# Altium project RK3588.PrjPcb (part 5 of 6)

## Sheet RK3588_USB2.0_USB3.0.SchDoc
size C; SheetNumber: 14; SheetTotal: 22
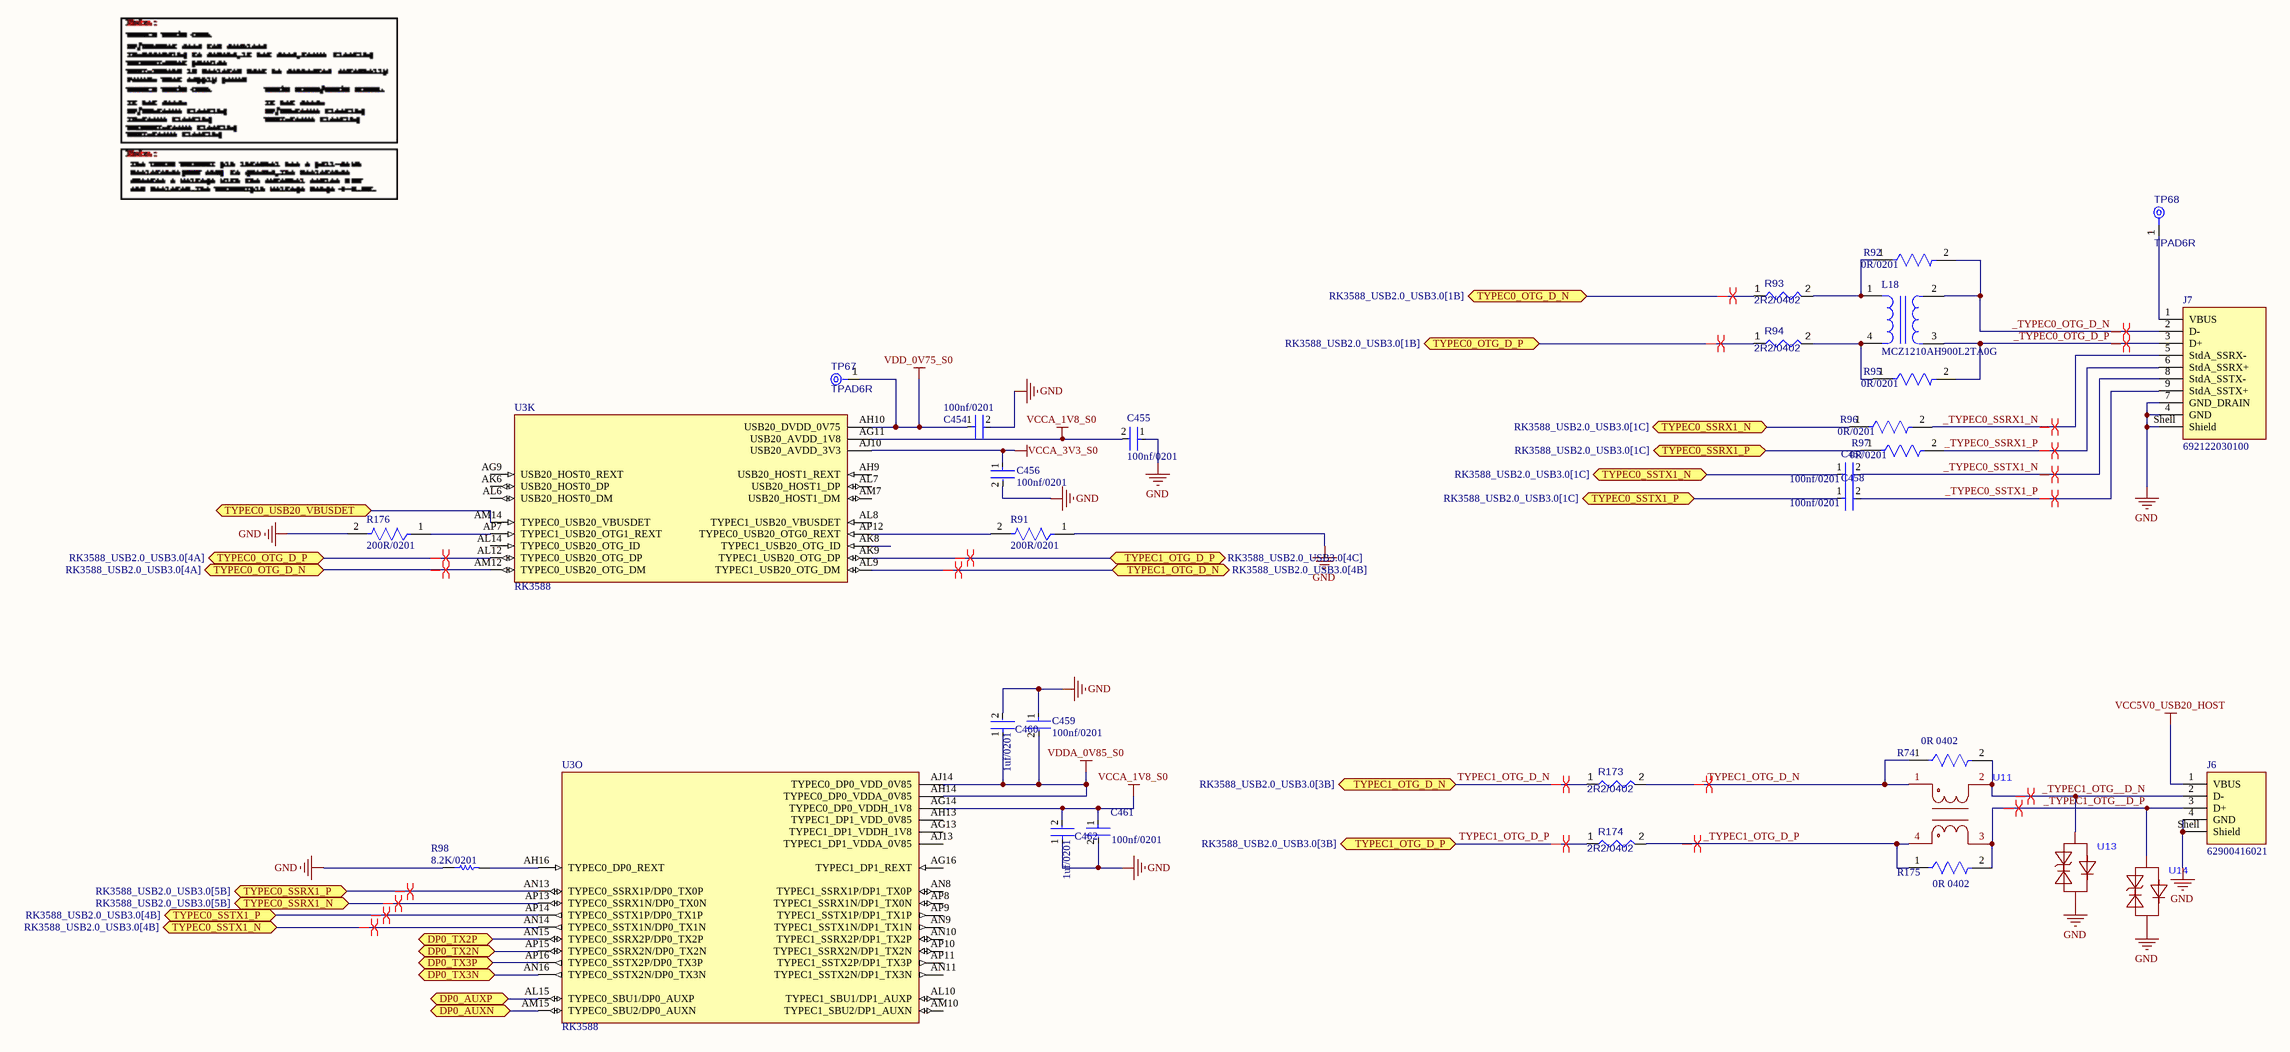
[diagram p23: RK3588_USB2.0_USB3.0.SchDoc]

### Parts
C454  100nf/0201  [FP-CL03-IPC_C]
C455  100nf/0201  [FP-CL03-IPC_C]
C456  100nf/0201  [FP-CL03-IPC_C]
C457  100nf/0201  [FP-CL03-IPC_C]
C458  100nf/0201  [FP-CL03-IPC_C]
C459  100nf/0201  [FP-CL03-IPC_C]
C460  1uf/0201  [FP-CC0201-BA-MFG]
C461  100nf/0201  [FP-CL03-IPC_C]
C462  1uf/0201  [FP-CC0201-BA-MFG]
J6  62900416021  [62900416021]
J7  692122030100  [692122030100]
L18  MCZ1210AH900L2TA0G  [FP-MCZ1210AH-MFG]
R74  0R 0402  [FP-AF0402-MFG]
R91  200R/0201  [FP-RT0201-MFG]
R92  0R/0201  [FP-RMCF0201-IPC_C]
R93  2R2/0402  [RESC0402(1005)_L]
R94  2R2/0402  [RESC0402(1005)_L]
R95  0R/0201  [FP-RMCF0201-IPC_C]
R96  0R/0201  [FP-RMCF0201-IPC_C]
R97  0R/0201  [FP-RMCF0201-IPC_C]
R98  8.2K/0201  [RESC0603X26X15ML03T05]
R173  2R2/0402  [RESC0402(1005)_L]
R174  2R2/0402  [RESC0402(1005)_L]
R175  0R 0402  [FP-AF0402-MFG]
R176  200R/0201  [FP-RT0201-MFG]
TP67  TPAD6R  [TP06R]  (no BOM)
TP68  TPAD6R  [TP06R]  (no BOM)
U3  RK3588  [BGA1088C65P34X34_2300X2300X204N]  (parts K,O of 30)
U11  (no value)  [FILTER-SMD_4P-L2.0-W1.3-BL_DLW21]
U13  (no value)  [DFN1006-2L-RD]
U14  (no value)  [DFN1006-2L-RD]

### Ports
DP0_AUXN (bidir), DP0_AUXP (bidir), DP0_TX2N (bidir), DP0_TX2P (bidir), DP0_TX3N (bidir), DP0_TX3P (bidir), TYPEC0_OTG_D_N (bidir, see RK3588_USB2.0_USB3.0[1B]), TYPEC0_OTG_D_N (bidir, see RK3588_USB2.0_USB3.0[4A]), TYPEC0_OTG_D_P (bidir, see RK3588_USB2.0_USB3.0[1B]), TYPEC0_OTG_D_P (bidir, see RK3588_USB2.0_USB3.0[4A]), TYPEC0_SSRX1_N (bidir, see RK3588_USB2.0_USB3.0[1C]), TYPEC0_SSRX1_N (bidir, see RK3588_USB2.0_USB3.0[5B]), TYPEC0_SSRX1_P (bidir, see RK3588_USB2.0_USB3.0[1C]), TYPEC0_SSRX1_P (bidir, see RK3588_USB2.0_USB3.0[5B]), TYPEC0_SSTX1_N (bidir, see RK3588_USB2.0_USB3.0[1C]), TYPEC0_SSTX1_N (bidir, see RK3588_USB2.0_USB3.0[4B]), TYPEC0_SSTX1_P (bidir, see RK3588_USB2.0_USB3.0[1C]), TYPEC0_SSTX1_P (bidir, see RK3588_USB2.0_USB3.0[4B]), TYPEC0_USB20_VBUSDET (bidir), TYPEC1_OTG_D_N (bidir, see RK3588_USB2.0_USB3.0[3B]), TYPEC1_OTG_D_N (bidir, see RK3588_USB2.0_USB3.0[4B]), TYPEC1_OTG_D_P (bidir, see RK3588_USB2.0_USB3.0[3B]), TYPEC1_OTG_D_P (bidir, see RK3588_USB2.0_USB3.0[4C])

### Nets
GND: C454.2 C455.1 C456.2 C459.1 C460.2 C461.2 C462.1 J6.4(GND) J6.Shell(Shield) J7.4(GND) J7.7(GND_DRAIN) J7.Shell(Shield) R91.1 R98.1 R176.2 U13.1 U14.1
VCC5V0_USB20_HOST: J6.1(VBUS)
VCCA_1V8_S0: C455.2 C461.1 C462.2 U3.AG11(USB20_AVDD_1V8) U3.AG14(TYPEC0_DP0_VDDH_1V8)  [project net VCCA_1V8]
VCCA_3V3_S0: C456.1 U3.AJ10(USB20_AVDD_3V3)  [project net PLDO4]
VDD_0V75_S0: C454.1 TP67.1(TP) U3.AH10(USB20_DVDD_0V75)  [project net NLDO5]
VDDA_0V85_S0: C459.2 C460.1 U3.AH14(TYPEC0_DP0_VDDA_0V85) U3.AJ14(TYPEC0_DP0_VDD_0V85)  [project net NLDO4]
_TYPEC0_OTG_D_N: J7.2(D-) L18.2 R92.2
_TYPEC0_OTG_D_P: J7.3(D+) L18.3 R95.2
_TYPEC0_SSRX1_N: J7.5(StdA_SSRX-) R96.2
_TYPEC0_SSRX1_P: J7.6(StdA_SSRX+) R97.2
_TYPEC0_SSTX1_N: C457.2 J7.8(StdA_SSTX-)
_TYPEC0_SSTX1_P: C458.2 J7.9(StdA_SSTX+)
_TYPEC1_OTG__D_N: J6.2(D-) R74.2 U11.2 U13.2
_TYPEC1_OTG__D_P: J6.3(D+) R175.2 U11.3 U14.2
_TYPEC1_OTG_D_N: R74.1 R173.2 U11.1
_TYPEC1_OTG_D_P: R174.2 R175.1 U11.4
DP0_AUXN: U3.AM15(TYPEC0_SBU2/DP0_AUXN) ; port DP0_AUXN
DP0_AUXP: U3.AL15(TYPEC0_SBU1/DP0_AUXP) ; port DP0_AUXP
DP0_TX2N: U3.AP15(TYPEC0_SSRX2N/DP0_TX2N) ; port DP0_TX2N
DP0_TX2P: U3.AN15(TYPEC0_SSRX2P/DP0_TX2P) ; port DP0_TX2P
DP0_TX3N: U3.AN16(TYPEC0_SSTX2N/DP0_TX3N) ; port DP0_TX3N
DP0_TX3P: U3.AP16(TYPEC0_SSTX2P/DP0_TX3P) ; port DP0_TX3P
TYPEC0_OTG_D_N: R93.1 U3.AM12(TYPEC0_USB20_OTG_DM) ; port TYPEC0_OTG_D_N
TYPEC0_OTG_D_P: R94.1 U3.AL12(TYPEC0_USB20_OTG_DP) ; port TYPEC0_OTG_D_P
TYPEC0_SSRX1_N: R96.1 U3.AP13(TYPEC0_SSRX1N/DP0_TX0N) ; port TYPEC0_SSRX1_N
TYPEC0_SSRX1_P: R97.1 U3.AN13(TYPEC0_SSRX1P/DP0_TX0P) ; port TYPEC0_SSRX1_P
TYPEC0_SSTX1_N: C457.1 U3.AN14(TYPEC0_SSTX1N/DP0_TX1N) ; port TYPEC0_SSTX1_N
TYPEC0_SSTX1_P: C458.1 U3.AP14(TYPEC0_SSTX1P/DP0_TX1P) ; port TYPEC0_SSTX1_P
TYPEC0_USB20_VBUSDET: U3.AM14(TYPEC0_USB20_VBUSDET) ; port TYPEC0_USB20_VBUSDET
TYPEC1_OTG_D_N: R173.1 U3.AL9(TYPEC1_USB20_OTG_DM) ; port TYPEC1_OTG_D_N
TYPEC1_OTG_D_P: R174.1 U3.AK9(TYPEC1_USB20_OTG_DP) ; port TYPEC1_OTG_D_P
NetJ7_1: J7.1(VBUS) TP68.1(TP)
NetL18_1: L18.1 R92.1 R93.2
NetL18_4: L18.4 R94.2 R95.1
NetR91_2: R91.2 U3.AP12(TYPEC0_USB20_OTG0_REXT)
NetR98_2: R98.2 U3.AH16(TYPEC0_DP0_REXT)
NetR176_1: R176.1 U3.AP7(TYPEC1_USB20_OTG1_REXT)

Not connected (* = marked no-connect by the designer): U3 AG9(USB20_HOST0_REXT) AG13(TYPEC1_DP1_VDDH_1V8) AG16(TYPEC1_DP1_REXT) AH9(USB20_HOST1_REXT) AH13(TYPEC1_DP1_VDD_0V85) AJ13(TYPEC1_DP1_VDDA_0V85) AK6(USB20_HOST0_DP) AK8(TYPEC1_USB20_OTG_ID) AL6(USB20_HOST0_DM) AL7(USB20_HOST1_DP) AL8(TYPEC1_USB20_VBUSDET) AL10(TYPEC1_SBU1/DP1_AUXP) AL14(TYPEC0_USB20_OTG_ID) AM7(USB20_HOST1_DM) AM10(TYPEC1_SBU2/DP1_AUXN) AN8(TYPEC1_SSRX1P/DP1_TX0P) AN9(TYPEC1_SSTX1N/DP1_TX1N) AN10(TYPEC1_SSRX2P/DP1_TX2P) AN11(TYPEC1_SSTX2N/DP1_TX3N) AP8(TYPEC1_SSRX1N/DP1_TX0N) AP9(TYPEC1_SSTX1P/DP1_TX1P) AP10(TYPEC1_SSRX2N/DP1_TX2N) AP11(TYPEC1_SSTX2P/DP1_TX3P)

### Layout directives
differential pair; differential pair class 90Ohm: _TYPEC0_OTG_D_N, _TYPEC0_OTG_D_P, _TYPEC0_SSRX1_N, _TYPEC0_SSRX1_P, _TYPEC0_SSTX1_N, _TYPEC0_SSTX1_P, _TYPEC1_OTG__D_N, _TYPEC1_OTG__D_P, _TYPEC1_OTG_D_N, _TYPEC1_OTG_D_P, TYPEC0_OTG_D_N, TYPEC0_OTG_D_P, TYPEC0_SSRX1_N, TYPEC0_SSRX1_P, TYPEC0_SSTX1_N, TYPEC0_SSTX1_P, TYPEC1_OTG_D_N, TYPEC1_OTG_D_P

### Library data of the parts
C454-C459 C461 = CMP-2010-00672-2: Cap Ceramic 100nF 10V X5R ±10% Pad SMD 0201 +85°C T/R; MN: CL03A104KP3NNNC
C460 C462 = CMP-03422-000660-2: 1uF 6.3V X5R ±20% 0201 Multilayer Ceramic Capacitors MLCC - SMD/SMT ROHS; Manufacturer: Yageo; Manufacturer Part Number: CC0201MRX5R5BB105; Tolerance: 0.2; Temperature Coefficient: 15%; MN: CL03A105MQ3CSNH
J6 = CMP-1502-03240-3: Wr-com; Right Angle Version 2.0; Connector SMT Socket, 30 V AC, 1.5A, 62900; Operating Supply Voltage: 30V; Contact Resistance: 20mΩ; Insulation Resistance: 1GΩ; Connector Type: USB; Number of Contacts: 4; Gender: Receptacle; USB Standard: USB 2.0
J7 = CMP-1502-03220-3: Conn USB 3.0 Type A RCP 9 POS 1.25mm Solder RA SMD 9 Terminal 1 Port T/R; Current Rating: 250mA; Insulation Resistance: 100MΩ; Number of Contacts: 9; Number of Ports: 1; Voltage Rating (AC): 30V; USB Standard: USB 3.0; Gender: Receptacle; Contact Resistance: 50mΩ
L18 = CMP-08256-000021-1: CMC 100MA 2LN 90 OHM SMD
R74 R175 = CMP-03412-048355-1: Anti-Sulfurated Chip Resistors Automotive Grade 0Ω 0402; Tolerance: 5%; MP: AF0402JR-070RL
R91 R176 = CMP-03412-012162-1: RES SMD 200 OHM 0.5% 1/20W 0201; Manufacturer Part Number: RT0201DRD07200RL; Manufacturer: Yageo; Tolerance: 0.005; Value: 200Ω; Power Rating: 0.05W; Voltage Rating: 25V; Temperature Coefficient: 25 ppm/°C
R92 R95-R97 = CMP-26527-001890-1: -55℃~+155℃ 0Ω 25V 50mW Thick Film Resistor 0201 Chip Resistor - Surface Mount ROHS; Resistance: 0R; MN: RMCF0201ZT0R00
R93 R94 R173 R174 = CMP-009-00088-2: 2R2 0.063W 5% 0402 (1005 Metric)  SMD; Power: 63mW; MN: CR0402JF02R2G
R98 = CMP-2004-01521-1: Manufacturer: KOA Speer; Part Number: RK73H1HTTC8201F
TP67 TP68 = CMP-00028-00002-2: 0.6mm round
U3 = RK3588: low power, high performance processor; MF: Fuzhou Rockchip Electronics Co
U11 = SDCW2012-2-900TF
U13 U14 = ESD5341N

## Sheet HDMI.SchDoc
size C; SheetNumber: 15; SheetTotal: 22
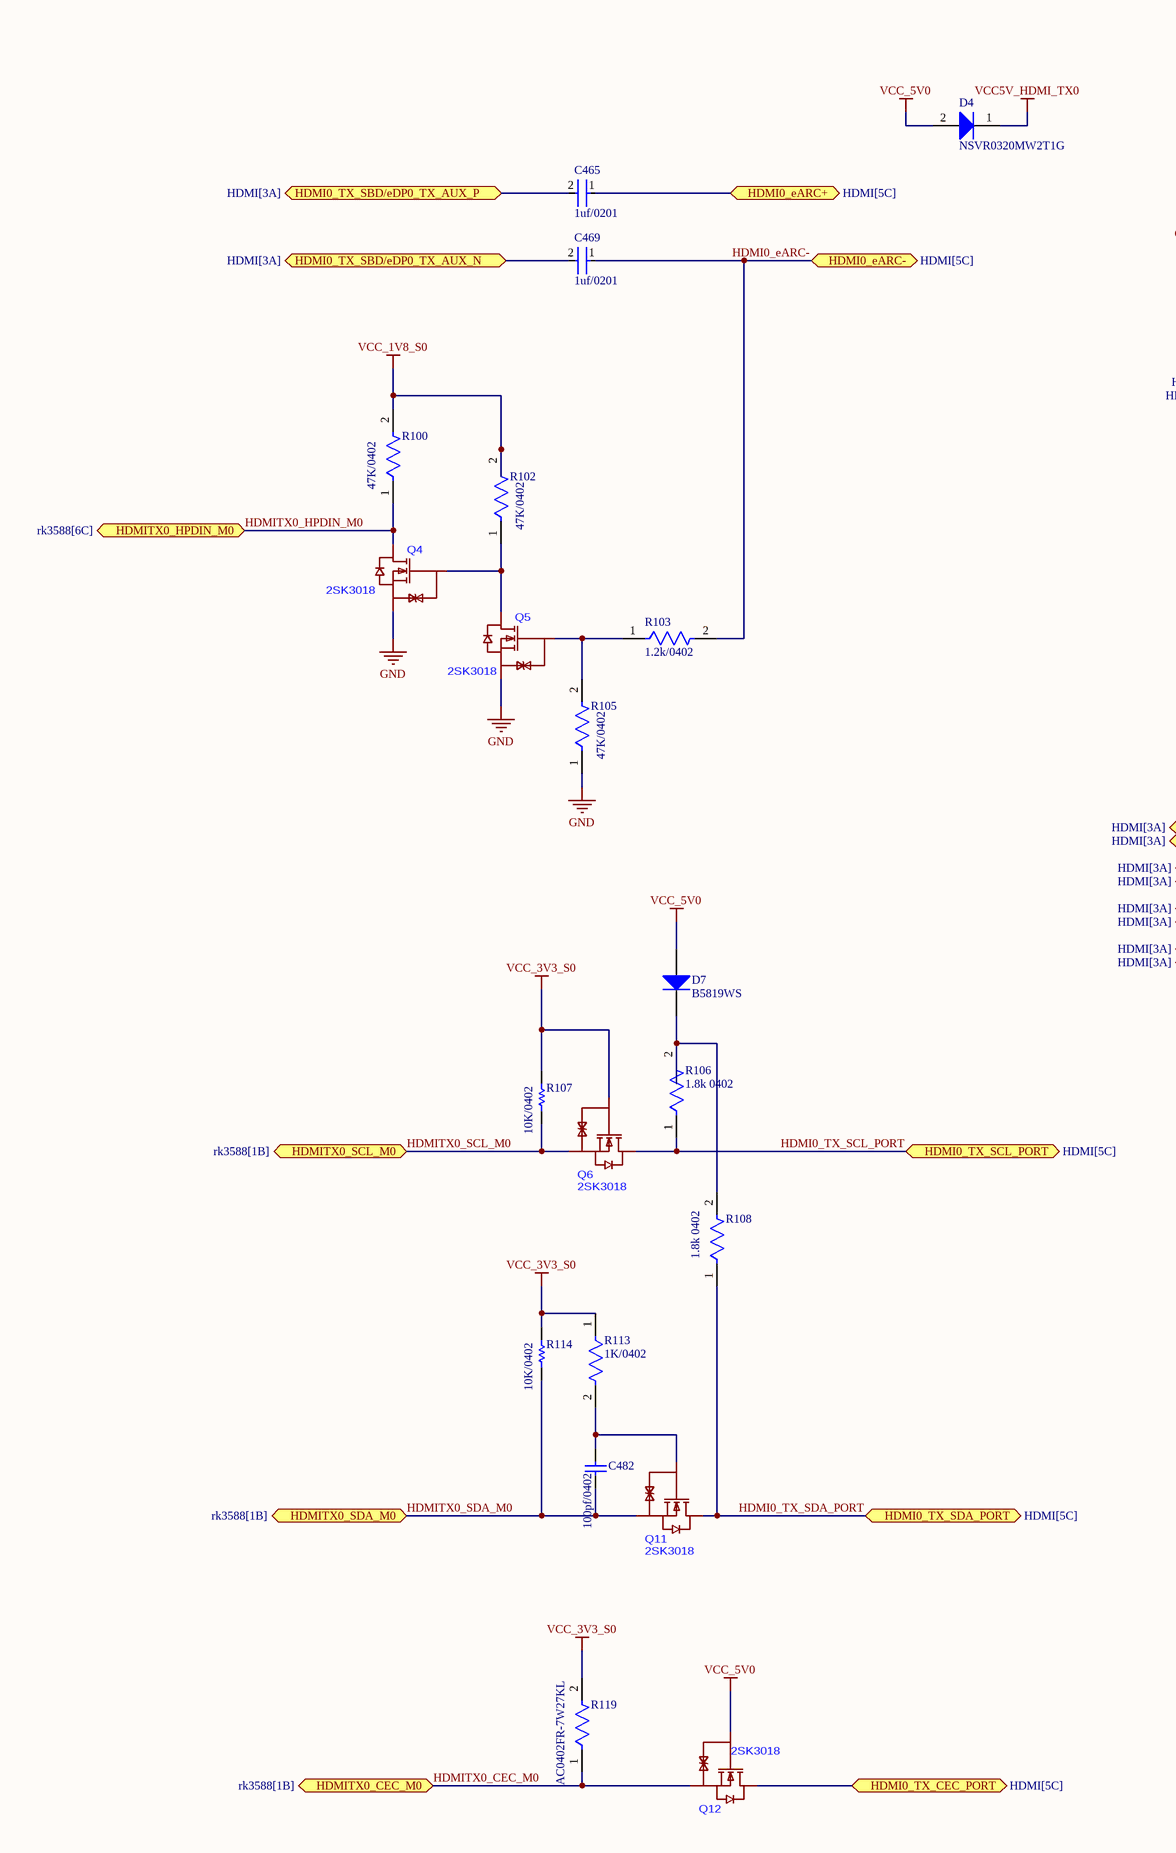
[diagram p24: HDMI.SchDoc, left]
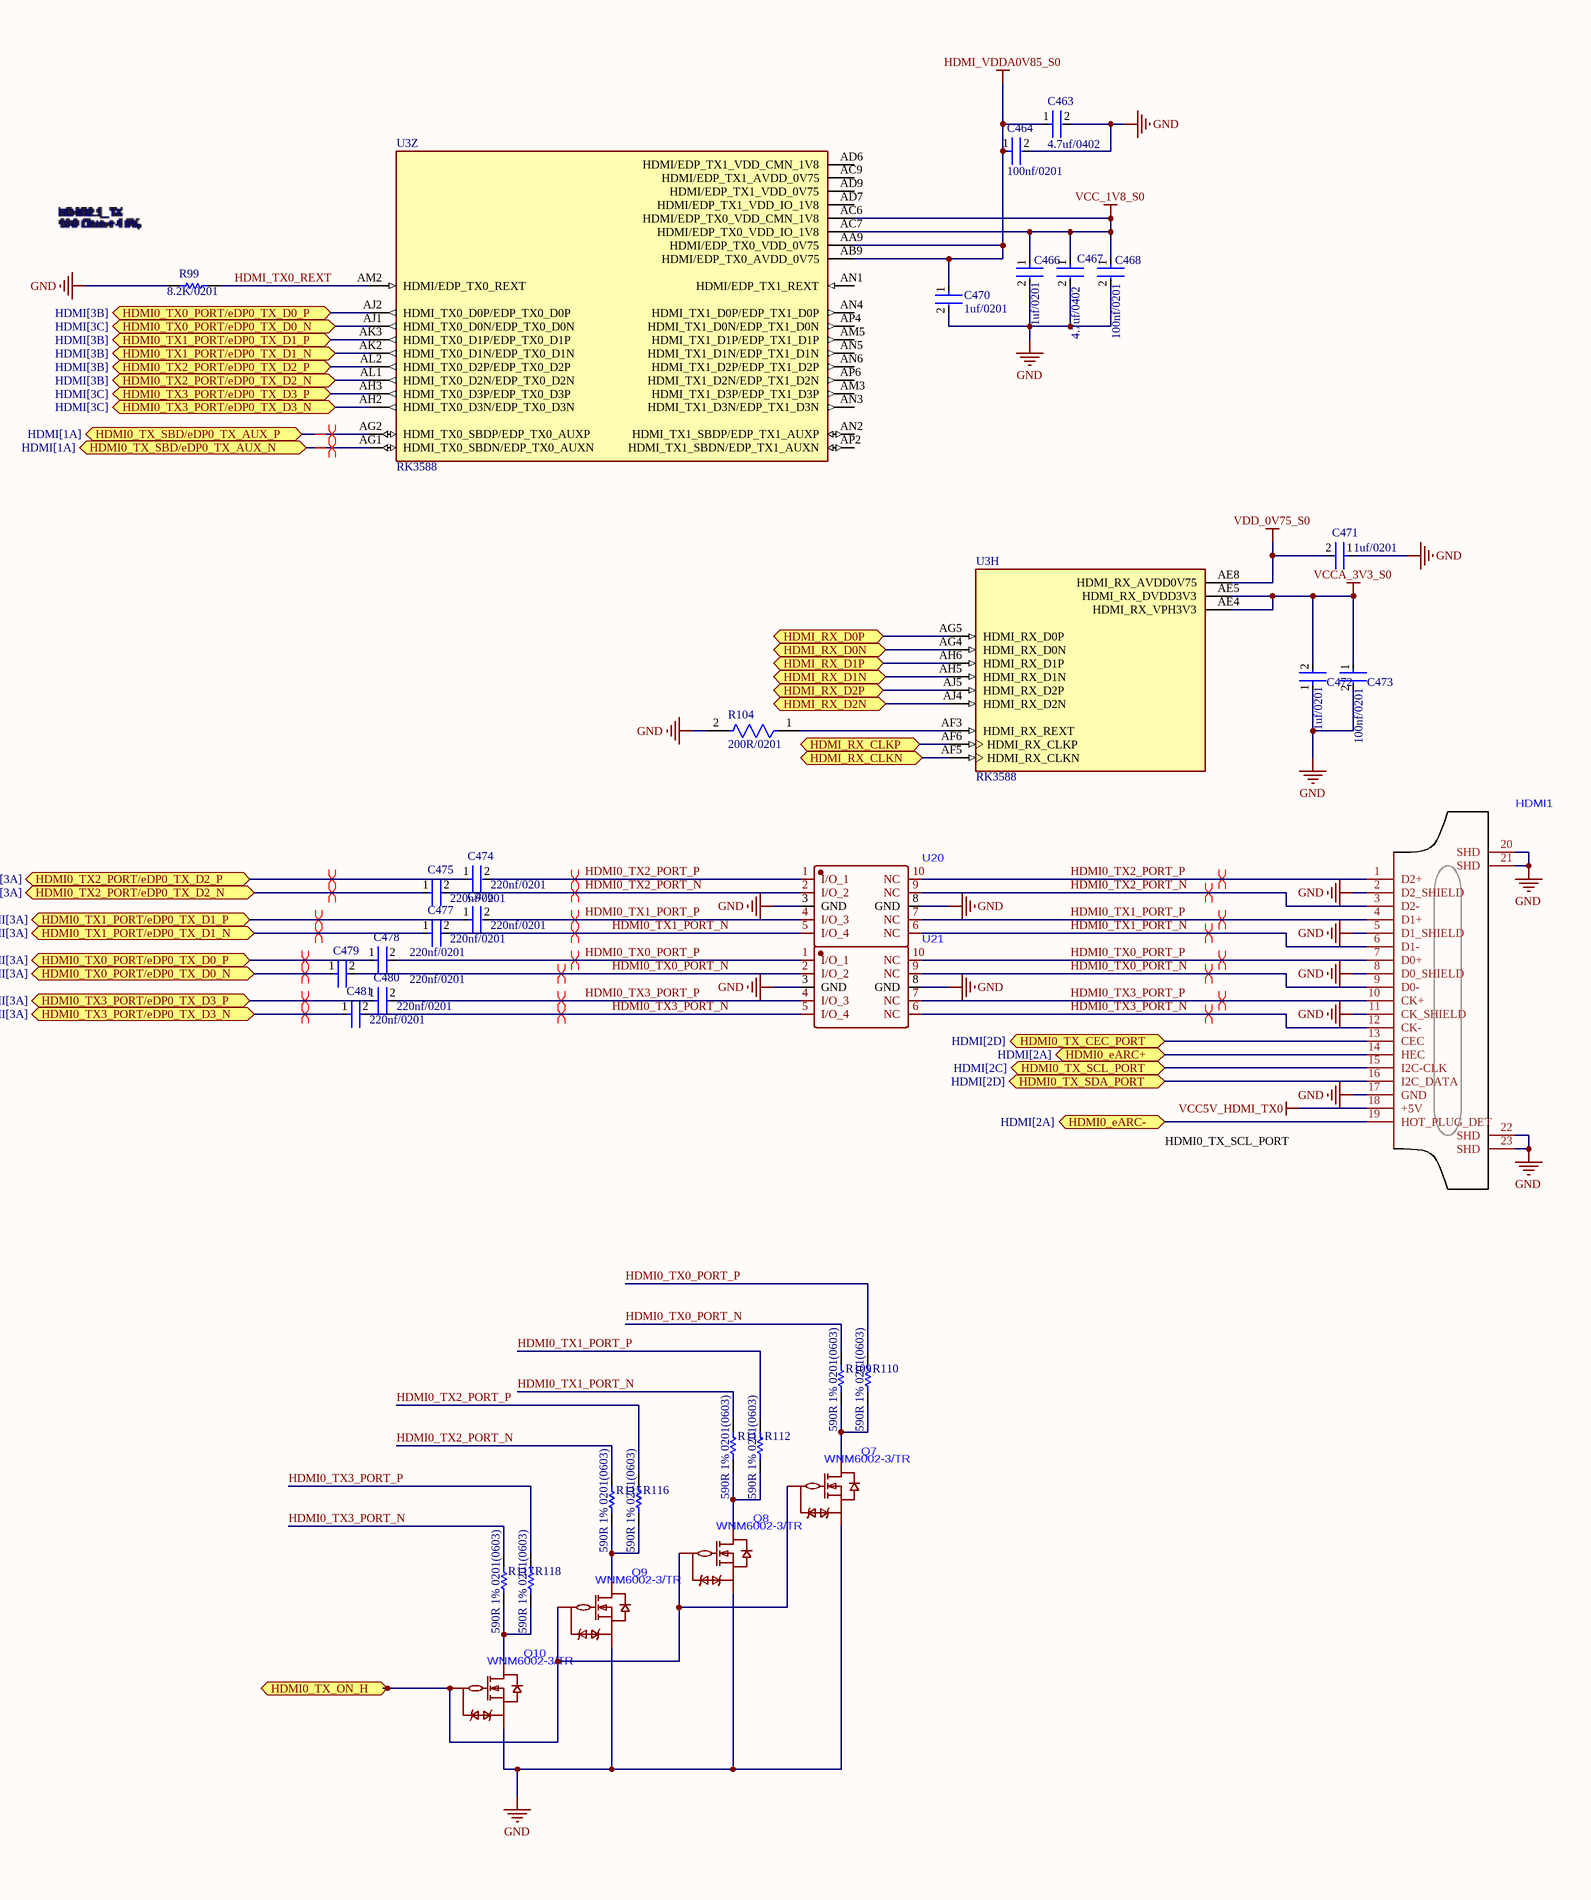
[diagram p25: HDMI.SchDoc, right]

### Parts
C463  4.7uf/0402  [FP-CC0402-MFG]
C464  100nf/0201  [FP-CL03-IPC_C]
C465  1uf/0201  [FP-CC0201-BA-MFG]
C466  1uf/0201  [FP-CC0201-BA-MFG]
C467  4.7uf/0402  [FP-CC0402-MFG]
C468  100nf/0201  [FP-CL03-IPC_C]
C469  1uf/0201  [FP-CC0201-BA-MFG]
C470  1uf/0201  [FP-CC0201-BA-MFG]
C471  1uf/0201  [FP-CC0201-BA-MFG]
C472  1uf/0201  [FP-CC0201-BA-MFG]
C473  100nf/0201  [FP-CL03-IPC_C]
C474  220nf/0201  [FP-CC0201-BA-MFG]
C475  220nf/0201  [FP-CC0201-BA-MFG]
C476  220nf/0201  [FP-CC0201-BA-MFG]
C477  220nf/0201  [FP-CC0201-BA-MFG]
C478  220nf/0201  [FP-CC0201-BA-MFG]
C479  220nf/0201  [FP-CC0201-BA-MFG]
C480  220nf/0201  [FP-CC0201-BA-MFG]
C481  220nf/0201  [FP-CC0201-BA-MFG]
C482  100pf/0402  [CAPC1005X55X25ML05T05]
D4  NSVR0320MW2T1G  [ONSC-SOD-323-2-477-02_V]
D7  B5819WS  [FAIR-SOD-323_V]
HDMI1  (no value)  [HDMI-SMD_HDMI-019S]
Q4  2SK3018  [SOT-23-3_L2.9-W1.3-P1.90-LS2.4-BR]
Q5  2SK3018  [SOT-23-3_L2.9-W1.3-P1.90-LS2.4-BR]
Q6  2SK3018  [SOT-23-3_L2.9-W1.3-P1.90-LS2.4-BR]
Q7  WNM6002-3/TR  [SOT-323-3_L2.0-W1.3-P1.30-LS2.1-BR]
Q8  WNM6002-3/TR  [SOT-323-3_L2.0-W1.3-P1.30-LS2.1-BR]
Q9  WNM6002-3/TR  [SOT-323-3_L2.0-W1.3-P1.30-LS2.1-BR]
Q10  WNM6002-3/TR  [SOT-323-3_L2.0-W1.3-P1.30-LS2.1-BR]
Q11  2SK3018  [SOT-23-3_L2.9-W1.3-P1.90-LS2.4-BR]
Q12  2SK3018  [SOT-23-3_L2.9-W1.3-P1.90-LS2.4-BR]
R99  8.2K/0201  [RESC0603X28X15NL05T05]
R100  47K/0402  [FP-CRCW0402-e3-IPC_B]
R102  47K/0402  [FP-CRCW0402-e3-IPC_B]
R103  1.2k/0402  [FP-RN73R1E-IPC_B]
R104  200R/0201  [FP-RT0201-MFG]
R105  47K/0402  [FP-CRCW0402-e3-IPC_B]
R106  1.8k 0402  [FP-RN73R1E-IPC_C]
R107  10K/0402  [RESC1005X40X25LL05T10]
R108  1.8k 0402  [FP-RN73R1E-IPC_C]
R109  590R 1% 0201(0603)  [RESC0201(0603)_L]
R110  590R 1% 0201(0603)  [RESC0201(0603)_L]
R111  590R 1% 0201(0603)  [RESC0201(0603)_L]
R112  590R 1% 0201(0603)  [RESC0201(0603)_L]
R113  1K/0402  [FP-AC0402-IPC_C]
R114  10K/0402  [RESC1005X40X25LL05T10]
R115  590R 1% 0201(0603)  [RESC0201(0603)_L]
R116  590R 1% 0201(0603)  [RESC0201(0603)_L]
R117  590R 1% 0201(0603)  [RESC0201(0603)_L]
R118  590R 1% 0201(0603)  [RESC0201(0603)_L]
R119  AC0402FR-7W27KL  [FP-AC0402-IPC_B]
U3  RK3588  [BGA1088C65P34X34_2300X2300X204N]  (parts H,Z of 30)
U20  (no value)  [DFN2510-10_L2.5-W1.0-P0.50-BL]
U21  (no value)  [DFN2510-10_L2.5-W1.0-P0.50-BL]

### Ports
HDMI0_eARC+ (bidir, see HDMI[2A]), HDMI0_eARC+ (bidir, see HDMI[5C]), HDMI0_eARC- (bidir, see HDMI[2A]), HDMI0_eARC- (bidir, see HDMI[5C]), HDMI0_TX0_PORT/eDP0_TX_D0_N (bidir, see HDMI[3A]), HDMI0_TX0_PORT/eDP0_TX_D0_N (bidir, see HDMI[3C]), HDMI0_TX0_PORT/eDP0_TX_D0_P (bidir, see HDMI[3A]), HDMI0_TX0_PORT/eDP0_TX_D0_P (bidir, see HDMI[3B]), HDMI0_TX1_PORT/eDP0_TX_D1_N (bidir, see HDMI[3A]), HDMI0_TX1_PORT/eDP0_TX_D1_N (bidir, see HDMI[3B]), HDMI0_TX1_PORT/eDP0_TX_D1_P (bidir, see HDMI[3A]), HDMI0_TX1_PORT/eDP0_TX_D1_P (bidir, see HDMI[3B]), HDMI0_TX2_PORT/eDP0_TX_D2_N (bidir, see HDMI[3A]), HDMI0_TX2_PORT/eDP0_TX_D2_N (bidir, see HDMI[3B]), HDMI0_TX2_PORT/eDP0_TX_D2_P (bidir, see HDMI[3A]), HDMI0_TX2_PORT/eDP0_TX_D2_P (bidir, see HDMI[3B]), HDMI0_TX3_PORT/eDP0_TX_D3_N (bidir, see HDMI[3A]), HDMI0_TX3_PORT/eDP0_TX_D3_N (bidir, see HDMI[3C]), HDMI0_TX3_PORT/eDP0_TX_D3_P (bidir, see HDMI[3A]), HDMI0_TX3_PORT/eDP0_TX_D3_P (bidir, see HDMI[3C]), HDMI0_TX_CEC_PORT (bidir, see HDMI[2D]), HDMI0_TX_CEC_PORT (bidir, see HDMI[5C]), HDMI0_TX_ON_H (bidir), HDMI0_TX_SBD/eDP0_TX_AUX_N (bidir, see HDMI[1A]), HDMI0_TX_SBD/eDP0_TX_AUX_N (bidir, see HDMI[3A]), HDMI0_TX_SBD/eDP0_TX_AUX_P (bidir, see HDMI[1A]), HDMI0_TX_SBD/eDP0_TX_AUX_P (bidir, see HDMI[3A]), HDMI0_TX_SCL_PORT (bidir, see HDMI[2C]), HDMI0_TX_SCL_PORT (bidir, see HDMI[5C]), HDMI0_TX_SDA_PORT (bidir, see HDMI[2D]), HDMI0_TX_SDA_PORT (bidir, see HDMI[5C]), HDMI_RX_CLKN (bidir), HDMI_RX_CLKP (bidir), HDMI_RX_D0N (bidir), HDMI_RX_D0P (bidir), HDMI_RX_D1N (bidir), HDMI_RX_D1P (bidir), HDMI_RX_D2N (bidir), HDMI_RX_D2P (bidir), HDMITX0_CEC_M0 (bidir, see rk3588[1B]), HDMITX0_HPDIN_M0 (bidir, see rk3588[6C]), HDMITX0_SCL_M0 (bidir, see rk3588[1B]), HDMITX0_SDA_M0 (bidir, see rk3588[1B])

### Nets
GND: C463.2 C464.2 C466.2 C467.2 C468.2 C470.2 C471.1 C472.1 C473.2 HDMI1.2(D2_SHIELD) HDMI1.5(D1_SHIELD) HDMI1.8(D0_SHIELD) HDMI1.11(CK_SHIELD) HDMI1.17(GND) HDMI1.20(SHD) HDMI1.21(SHD) HDMI1.22(SHD) HDMI1.23(SHD) Q4.2(S) Q5.2(S) Q7.2(S) Q8.2(S) Q9.2(S) Q10.2(S) R99.1 R104.2 R105.1 U20.3(GND) U20.8(GND) U21.3(GND) U21.8(GND)
HDMI_VDDA0V85_S0: C463.1 C464.1 C470.1 U3.AA9(HDMI/EDP_TX0_VDD_0V75) U3.AB9(HDMI/EDP_TX0_AVDD_0V75)  [project net NLDO3]
VCC5V_HDMI_TX0: D4.1(K) HDMI1.18(+5V)
VCC_1V8_S0: C466.1 C467.1 C468.1 R100.2 R102.2 U3.AC6(HDMI/EDP_TX0_VDD_CMN_1V8) U3.AC7(HDMI/EDP_TX0_VDD_IO_1V8)
VCC_3V3_S0: Q6.1(G) R107.1 R113.1 R114.1 R119.2
VCC_5V0: D4.2(A) D7.1(A) Q12.1(G)
VCCA_3V3_S0: C472.2 C473.1 U3.AE4(HDMI_RX_VPH3V3) U3.AE5(HDMI_RX_DVDD3V3)  [project net PLDO4]
VDD_0V75_S0: C471.2 U3.AE8(HDMI_RX_AVDD0V75)  [project net NLDO5]
HDMI0_eARC+: C465.1 HDMI1.14(HEC) ; port HDMI0_eARC+
HDMI0_eARC-: C469.1 HDMI1.19(HOT_PLUG_DET) R103.2 ; port HDMI0_eARC-
HDMI0_TX0_PORT/eDP0_TX_D0_N: C479.1 U3.AJ1(HDMI_TX0_D0N/EDP_TX0_D0N) ; port HDMI0_TX0_PORT/eDP0_TX_D0_N
HDMI0_TX0_PORT/eDP0_TX_D0_P: C478.1 U3.AJ2(HDMI_TX0_D0P/EDP_TX0_D0P) ; port HDMI0_TX0_PORT/eDP0_TX_D0_P
HDMI0_TX0_PORT_N: C479.2 HDMI1.9(D0-) R109.2 U21.2(I/O_2) U21.9(NC)
HDMI0_TX0_PORT_P: C478.2 HDMI1.7(D0+) R110.2 U21.1(I/O_1) U21.10(NC)
HDMI0_TX1_PORT/eDP0_TX_D1_N: C477.1 U3.AK2(HDMI_TX0_D1N/EDP_TX0_D1N) ; port HDMI0_TX1_PORT/eDP0_TX_D1_N
HDMI0_TX1_PORT/eDP0_TX_D1_P: C476.1 U3.AK3(HDMI_TX0_D1P/EDP_TX0_D1P) ; port HDMI0_TX1_PORT/eDP0_TX_D1_P
HDMI0_TX1_PORT_N: C477.2 HDMI1.6(D1-) R111.2 U20.5(I/O_4) U20.6(NC)
HDMI0_TX1_PORT_P: C476.2 HDMI1.4(D1+) R112.2 U20.4(I/O_3) U20.7(NC)
HDMI0_TX2_PORT/eDP0_TX_D2_N: C475.1 U3.AL1(HDMI_TX0_D2N/EDP_TX0_D2N) ; port HDMI0_TX2_PORT/eDP0_TX_D2_N
HDMI0_TX2_PORT/eDP0_TX_D2_P: C474.1 U3.AL2(HDMI_TX0_D2P/EDP_TX0_D2P) ; port HDMI0_TX2_PORT/eDP0_TX_D2_P
HDMI0_TX2_PORT_N: C475.2 HDMI1.3(D2-) R115.2 U20.2(I/O_2) U20.9(NC)
HDMI0_TX2_PORT_P: C474.2 HDMI1.1(D2+) R116.2 U20.1(I/O_1) U20.10(NC)
HDMI0_TX3_PORT/eDP0_TX_D3_N: C481.1 U3.AH2(HDMI_TX0_D3N/EDP_TX0_D3N) ; port HDMI0_TX3_PORT/eDP0_TX_D3_N
HDMI0_TX3_PORT/eDP0_TX_D3_P: C480.1 U3.AH3(HDMI_TX0_D3P/EDP_TX0_D3P) ; port HDMI0_TX3_PORT/eDP0_TX_D3_P
HDMI0_TX3_PORT_N: C481.2 HDMI1.12(CK-) R117.2 U21.5(I/O_4) U21.6(NC)
HDMI0_TX3_PORT_P: C480.2 HDMI1.10(CK+) R118.2 U21.4(I/O_3) U21.7(NC)
HDMI0_TX_CEC_PORT: HDMI1.13(CEC) Q12.3(D) ; port HDMI0_TX_CEC_PORT
HDMI0_TX_ON_H: Q7.1(G) Q8.1(G) Q9.1(G) Q10.1(G) ; port HDMI0_TX_ON_H
HDMI0_TX_SBD/eDP0_TX_AUX_N: C469.2 U3.AG1(HDMI_TX0_SBDN/EDP_TX0_AUXN) ; port HDMI0_TX_SBD/eDP0_TX_AUX_N
HDMI0_TX_SBD/eDP0_TX_AUX_P: C465.2 U3.AG2(HDMI_TX0_SBDP/EDP_TX0_AUXP) ; port HDMI0_TX_SBD/eDP0_TX_AUX_P
HDMI0_TX_SCL_PORT: HDMI1.15(I2C-CLK) Q6.3(D) R106.1 ; port HDMI0_TX_SCL_PORT
HDMI0_TX_SDA_PORT: HDMI1.16(I2C_DATA) Q11.3(D) R108.1 ; port HDMI0_TX_SDA_PORT
HDMI_RX_CLKN: U3.AF5(HDMI_RX_CLKN) ; port HDMI_RX_CLKN
HDMI_RX_CLKP: U3.AF6(HDMI_RX_CLKP) ; port HDMI_RX_CLKP
HDMI_RX_D0N: U3.AG4(HDMI_RX_D0N) ; port HDMI_RX_D0N
HDMI_RX_D0P: U3.AG5(HDMI_RX_D0P) ; port HDMI_RX_D0P
HDMI_RX_D1N: U3.AH5(HDMI_RX_D1N) ; port HDMI_RX_D1N
HDMI_RX_D1P: U3.AH6(HDMI_RX_D1P) ; port HDMI_RX_D1P
HDMI_RX_D2N: U3.AJ4(HDMI_RX_D2N) ; port HDMI_RX_D2N
HDMI_RX_D2P: U3.AJ5(HDMI_RX_D2P) ; port HDMI_RX_D2P
HDMI_TX0_REXT: R99.2 U3.AM2(HDMI/EDP_TX0_REXT)
HDMITX0_CEC_M0: Q12.2(S) R119.1 ; port HDMITX0_CEC_M0
HDMITX0_HPDIN_M0: Q4.3(D) R100.1 ; port HDMITX0_HPDIN_M0
HDMITX0_SCL_M0: Q6.2(S) R107.2 ; port HDMITX0_SCL_M0
HDMITX0_SDA_M0: C482.1 Q11.2(S) R114.2 ; port HDMITX0_SDA_M0
NetC482_2: C482.2 Q11.1(G) R113.2
NetD7_2: D7.2(K) R106.2 R108.2
NetQ4_1: Q4.1(G) Q5.3(D) R102.1
NetQ5_1: Q5.1(G) R103.1 R105.2
NetQ7_3: Q7.3(D) R109.1 R110.1
NetQ8_3: Q8.3(D) R111.1 R112.1
NetQ9_3: Q9.3(D) R115.1 R116.1
NetQ10_3: Q10.3(D) R117.1 R118.1
NetR104_1: R104.1 U3.AF3(HDMI_RX_REXT)

Not connected (* = marked no-connect by the designer): U3 AC9(HDMI/EDP_TX1_AVDD_0V75) AD6(HDMI/EDP_TX1_VDD_CMN_1V8) AD7(HDMI/EDP_TX1_VDD_IO_1V8) AD9(HDMI/EDP_TX1_VDD_0V75) AM3(HDMI_TX1_D3P/EDP_TX1_D3P) AM5(HDMI_TX1_D1P/EDP_TX1_D1P) AN1(HDMI/EDP_TX1_REXT) AN2(HDMI_TX1_SBDP/EDP_TX1_AUXP) AN3(HDMI_TX1_D3N/EDP_TX1_D3N) AN4(HDMI_TX1_D0P/EDP_TX1_D0P) AN5(HDMI_TX1_D1N/EDP_TX1_D1N) AN6(HDMI_TX1_D2P/EDP_TX1_D2P) AP2(HDMI_TX1_SBDN/EDP_TX1_AUXN) AP4(HDMI_TX1_D0N/EDP_TX1_D0N) AP6(HDMI_TX1_D2N/EDP_TX1_D2N)

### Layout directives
differential pair; differential pair class HDMI_100: HDMI0_TX0_PORT/eDP0_TX_D0_N, HDMI0_TX0_PORT/eDP0_TX_D0_P, HDMI0_TX0_PORT_N, HDMI0_TX0_PORT_P, HDMI0_TX1_PORT/eDP0_TX_D1_N, HDMI0_TX1_PORT/eDP0_TX_D1_P, HDMI0_TX1_PORT_N, HDMI0_TX1_PORT_P, HDMI0_TX2_PORT/eDP0_TX_D2_N, HDMI0_TX2_PORT/eDP0_TX_D2_P, HDMI0_TX2_PORT_N, HDMI0_TX2_PORT_P, HDMI0_TX3_PORT/eDP0_TX_D3_N, HDMI0_TX3_PORT/eDP0_TX_D3_P, HDMI0_TX3_PORT_N, HDMI0_TX3_PORT_P, HDMI0_TX_SBD/eDP0_TX_AUX_N, HDMI0_TX_SBD/eDP0_TX_AUX_P

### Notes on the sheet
- HDMI0_TX_SCL_PORT

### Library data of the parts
C463 C467 = CMP-03422-000823-1: 10V 4.7uF X5R ±10% 0402 Multilayer Ceramic Capacitors MLCC - SMD/SMT ROHS; Manufacturer Part Number: CC0402KRX5R6BB475; Manufacturer: YAGEO; Automotive Grade: NA; Temperature Coefficient: 30ppm/°C; Tolerance: 0.1
C464 C468 C473 = CMP-2010-00672-2: as C454-C459 on sheet RK3588_USB2.0_USB3.0
C465 C466 C469-C472 = CMP-03422-000660-2: as C460 on sheet RK3588_USB2.0_USB3.0
C474-C481 = CMP-03422-000318-1: CC0201 220 nF X5R 10.00% 10 V; Manufacturer: Yageo; Material: Ceramic; Capacitance: 220 nF; MN: CC0201KRX5R6BB224; Voltage Rating: 10 V; Temperature Coefficient: 15%; Value: 220 nF; Tolerance: 0.1
C482 = CMP-2008-01233-1: Part Number: VJ0402Y101KXAPW1BC; Manufacturer: Vitramon
D4 = CMP-1055-00467-1: Schottky Barrier Diode, 2-Pin SOD-323, Pb-Free, Tape and Reel; Manufacturer: On Semiconductor; IFSM Max (A): 5; Configuration: Single
D7 = CMP-004-00001-2: -55℃~+125℃ 1.5A 1A 40V 600mV@1A Independent SOD-323 Schottky Diodes ROHS; Manufacturer: Fairchild; Recovery Time: 4ns; Forward Voltage: 1V; Peak Reverse Current: 5uA; Forward Current: 150mA; Capacitance: -323f
HDMI1 = HDMI-019S
R99 = CMP-2004-00919-1: Manufacturer: Vishay Dale; Part Number: CRCW02018K20FKED
R100 R102 R105 = CMP-02407-007381-1: RES Thick Film, 47kΩ, 1%, 0.063W, 100ppm/°C, 0402; Max Power Dissipation: 63mW; Resistance: 47kR
R103 = CMP-04015-066543-1: 1.2kΩ ±1% 0.063W, 1/16W Chip Resistor 0402 (1005 Metric) Moisture Resistant Thin Film
R104 = CMP-03412-012162-1: as R91 on sheet RK3588_USB2.0_USB3.0
R106 R108 = CMP-04015-046155-1: 1.8kΩ ±0.1% 0.063W, 1/16W Chip Resistor 0402 (1005 Metric) Moisture Resistant Thin Film; MN: RN73R1ETTP1801B25
R107 R114 = CMP-2002-07353-1: -55℃~+155℃ 10kΩ 50V 62.5mW Thick Film Resistor ±1% ±100ppm/℃ 0402 Chip Resistor - Surface Mount ROHS; Part Number: RC0402FR-0710KL; Manufacturer: Yageo / Phycomp
R109-R112 R115-R118 = CMP-1010-00390-1: 590R 0.05W 1% 0201 (0603 Metric)  SMD; Case-Metric: 0603; Case-EIA: 0201; Value: 590.00 Ohm; MN: RC-01W5900FT
R113 = CMP-03412-047873-1: RES 1kΩ ±1% 0.063W 0402
R119 = CMP-03412-041263-1: RES 27kΩ ±1% 0.125W 0402
U3 = RK3588: as U3 on sheet RK3588_USB2.0_USB3.0
U20 U21 = ESD5304D

## Sheet Discrete Power.SchDoc
size C; SheetNumber: 16; SheetTotal: 22
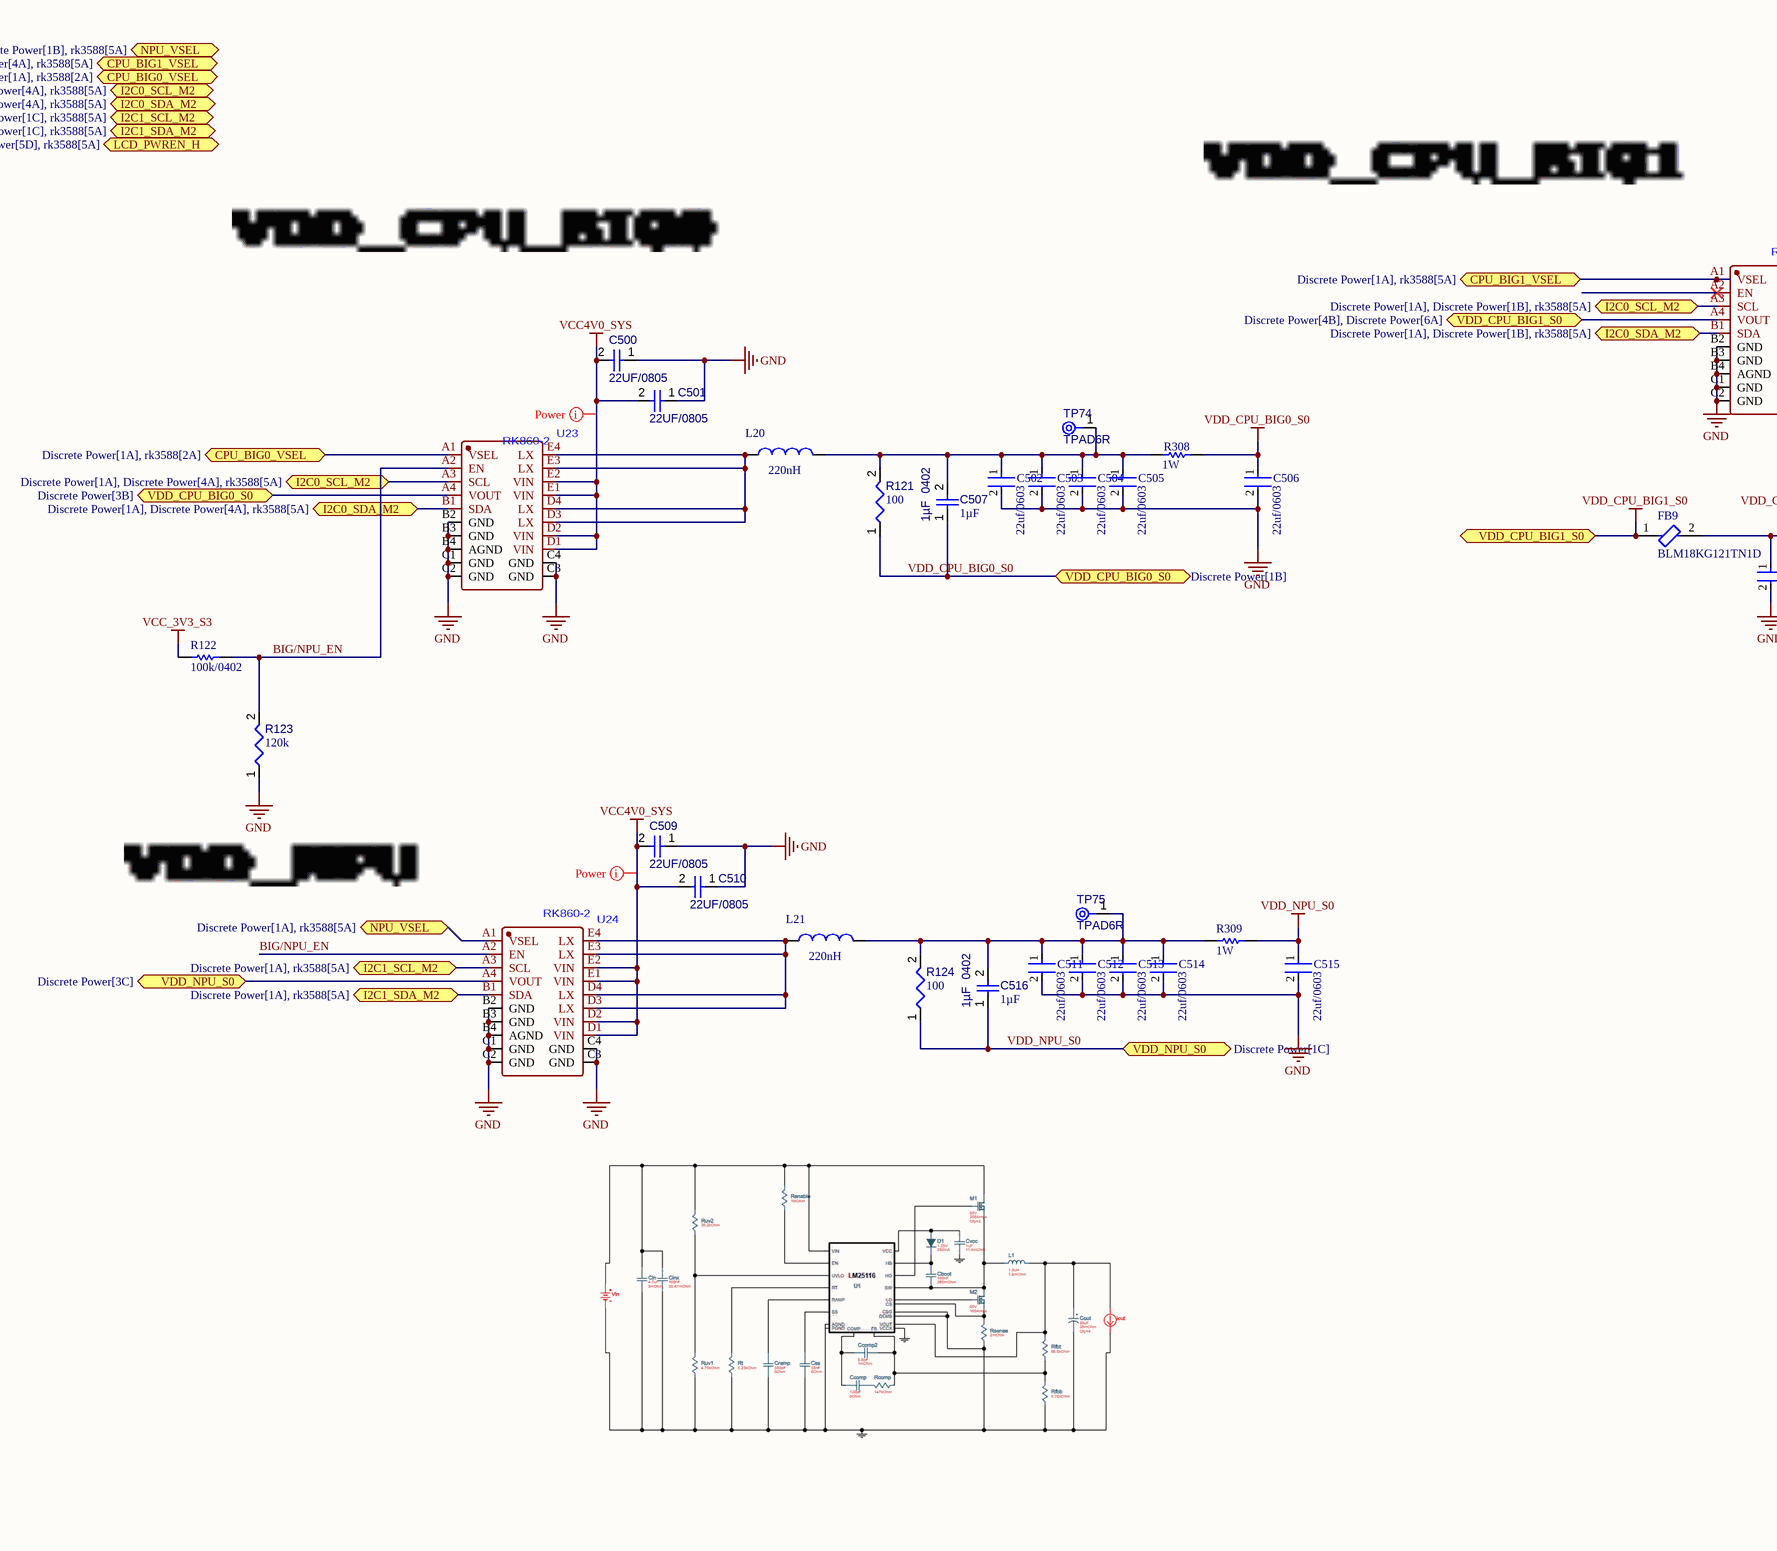
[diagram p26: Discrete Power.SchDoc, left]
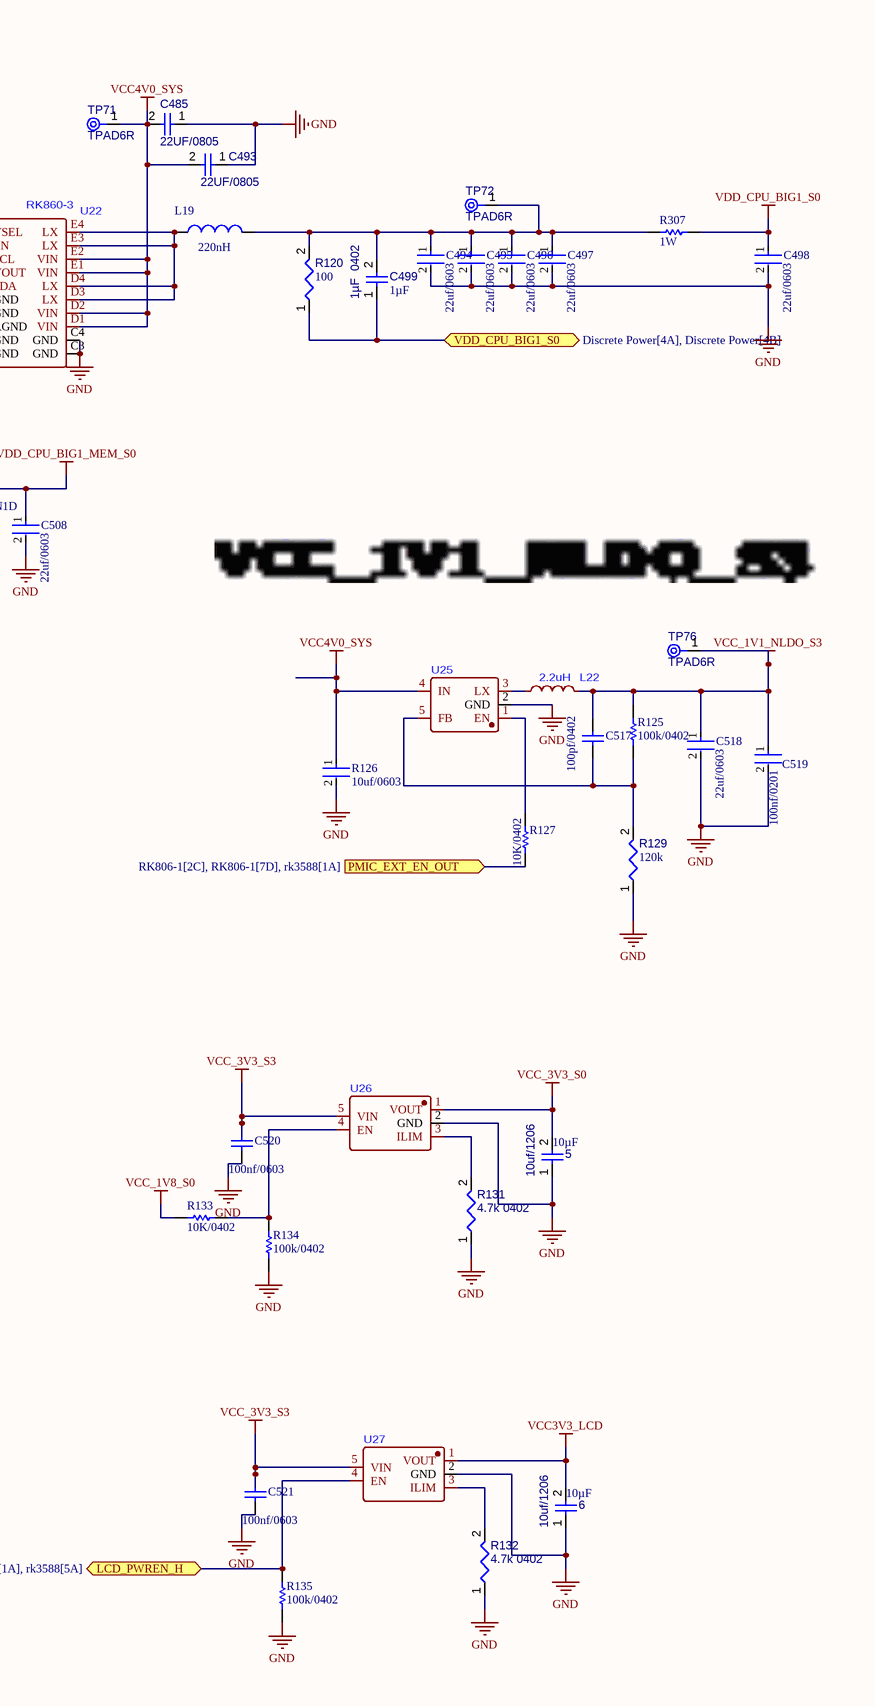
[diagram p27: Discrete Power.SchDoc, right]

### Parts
5  10uf/1206  value 10µF  [CAPC3216X180X50NL20T25]
6  10uf/1206  value 10µF  [CAPC3216X180X50NL20T25]
C485  22UF/0805  [CAPC0805(2012)145_L]
C493  22UF/0805  [CAPC0805(2012)145_L]
C494  22uf/0603  [FP-GRM188-0_2-MFG]
C495  22uf/0603  [FP-GRM188-0_2-MFG]
C496  22uf/0603  [FP-GRM188-0_2-MFG]
C497  22uf/0603  [FP-GRM188-0_2-MFG]
C498  22uf/0603  [FP-GRM188-0_2-MFG]
C499  1µF  0402  value 1µF  [CAPC0402(1005)60_L]
C500  22UF/0805  [CAPC0805(2012)145_L]
C501  22UF/0805  [CAPC0805(2012)145_L]
C502  22uf/0603  [FP-GRM188-0_2-MFG]
C503  22uf/0603  [FP-GRM188-0_2-MFG]
C504  22uf/0603  [FP-GRM188-0_2-MFG]
C505  22uf/0603  [FP-GRM188-0_2-MFG]
C506  22uf/0603  [FP-GRM188-0_2-MFG]
C507  1µF  0402  value 1µF  [CAPC0402(1005)60_L]
C508  22uf/0603  [FP-GRM188-0_2-MFG]
C509  22UF/0805  [CAPC0805(2012)145_L]
C510  22UF/0805  [CAPC0805(2012)145_L]
C511  22uf/0603  [FP-GRM188-0_2-MFG]
C512  22uf/0603  [FP-GRM188-0_2-MFG]
C513  22uf/0603  [FP-GRM188-0_2-MFG]
C514  22uf/0603  [FP-GRM188-0_2-MFG]
C515  22uf/0603  [FP-GRM188-0_2-MFG]
C516  1µF  0402  value 1µF  [CAPC0402(1005)60_L]
C517  100pf/0402  [CAPC1005X55X25ML05T05]
C518  22uf/0603  [FP-GRM188-0_2-MFG]
C519  100nf/0201  [FP-CL03-IPC_C]
C520  100nf/0603  [CAPC1608X92X38ML15T08]
C521  100nf/0603  [CAPC1608X92X38ML15T08]
FB9  BLM18KG121TN1D  [FP-BLM18-0_15-t0_6-d1_2-IPC_A]
L19  220nH  [WE-HCC_1210]
L20  220nH  [WE-HCC_1210]
L21  220nH  [WE-HCC_1210]
L22  2.2uH  [IND-SMD_L4.0-W4.0]
R120  value 100  [RESC0402(1005)_L]  (hidden comment: 100R / 0402)
R121  value 100  [RESC0402(1005)_L]  (hidden comment: 100R / 0402)
R122  100k/0402  [RESC1005X40X25NL05T10]
R123  value 120k  [RESC0402(1005)_L]  (hidden comment: 120k/0402)
R124  value 100  [RESC0402(1005)_L]  (hidden comment: 100R / 0402)
R125  100k/0402  [RESC1005X40X25NL05T10]
R126  10uf/0603  [FP-CC0603-DC-MFG]
R127  10K/0402  [RESC1005X40X25LL05T10]
R129  value 120k  [RESC0402(1005)_L]  (hidden comment: 120k/0402)
R131  4.7k 0402  [RESC0402(1005)_L]
R132  4.7k 0402  [RESC0402(1005)_L]
R133  10K/0402  [RESC1005X40X25LL05T10]
R134  100k/0402  [RESC1005X40X25NL05T10]
R135  100k/0402  [RESC1005X40X25NL05T10]
R307  value 1W  [RESC3216X60X45ML15T20]  (hidden comment: HoYH1206-1W-10mR-1%)
R308  value 1W  [RESC3216X60X45ML15T20]  (hidden comment: HoYH1206-1W-10mR-1%)
R309  value 1W  [RESC3216X60X45ML15T20]  (hidden comment: HoYH1206-1W-10mR-1%)
TP71  TPAD6R  [TP06R]  (no BOM)
TP72  TPAD6R  [TP06R]  (no BOM)
TP74  TPAD6R  [TP06R]  (no BOM)
TP75  TPAD6R  [TP06R]  (no BOM)
TP76  TPAD6R  [TP06R]  (no BOM)
U22  RK860-3  [WLCSP-20_L2.0-W1.6-R5-C4-P0.40-TL]
U23  RK860-2  [WLCSP-20_L2.0-W1.6-R5-C4-P0.40-TL]
U24  RK860-2  [WLCSP-20_L2.0-W1.6-R5-C4-P0.40-TL]
U25  (no value)  [SOT-23-5_L2.9-W1.6-P0.95-LS2.8-BL]
U26  (no value)  [SOT-23-5_L2.9-W1.6-P0.95-LS2.8-TL]
U27  (no value)  [SOT-23-5_L2.9-W1.6-P0.95-LS2.8-TL]

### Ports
CPU_BIG0_VSEL (bidir, see Discrete Power[1A], rk3588[2A]), CPU_BIG1_VSEL (bidir, see Discrete Power[1A], rk3588[5A]), CPU_BIG1_VSEL (bidir, see Discrete Power[4A], rk3588[5A]), I2C0_SCL_M2 (bidir, see Discrete Power[1A], Discrete Power[1B], rk3588[5A]), I2C0_SCL_M2 (bidir, see Discrete Power[1A], Discrete Power[4A], rk3588[5A]), I2C0_SCL_M2 (bidir, see Discrete Power[1B], Discrete Power[4A], rk3588[5A]), I2C0_SDA_M2 (bidir, see Discrete Power[1A], Discrete Power[1B], rk3588[5A]), I2C0_SDA_M2 (bidir, see Discrete Power[1A], Discrete Power[4A], rk3588[5A]), I2C0_SDA_M2 (bidir, see Discrete Power[1B], Discrete Power[4A], rk3588[5A]), I2C1_SCL_M2 (bidir, see Discrete Power[1A], rk3588[5A]), I2C1_SCL_M2 (bidir, see Discrete Power[1C], rk3588[5A]), I2C1_SDA_M2 (bidir, see Discrete Power[1A], rk3588[5A]), I2C1_SDA_M2 (bidir, see Discrete Power[1C], rk3588[5A]), LCD_PWREN_H (bidir, see Discrete Power[1A], rk3588[5A]), LCD_PWREN_H (bidir, see Discrete Power[5D], rk3588[5A]), NPU_VSEL (bidir, see Discrete Power[1A], rk3588[5A]), NPU_VSEL (bidir, see Discrete Power[1B], rk3588[5A]), PMIC_EXT_EN_OUT (in, see RK806-1[2C], RK806-1[7D], rk3588[1A]), VDD_CPU_BIG0_S0 (bidir, see Discrete Power[1B]), VDD_CPU_BIG0_S0 (bidir, see Discrete Power[3B]), VDD_CPU_BIG1_S0 (bidir, see Discrete Power[4A], Discrete Power[4B]), VDD_CPU_BIG1_S0 (bidir, see Discrete Power[4A], Discrete Power[6A]), VDD_CPU_BIG1_S0 (bidir, see Discrete Power[4B], Discrete Power[6A]), VDD_NPU_S0 (bidir, see Discrete Power[1C]), VDD_NPU_S0 (bidir, see Discrete Power[3C])

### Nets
GND: 5.1 6.1 C485.1 C493.1 C494.2 C495.2 C496.2 C497.2 C498.2 C500.1 C501.1 C502.2 C503.2 C504.2 C505.2 C506.2 C508.2 C509.1 C510.1 C511.2 C512.2 C513.2 C514.2 C515.2 C518.2 C519.2 C520.1 C521.1 R123.1 R126.2 R129.1 R131.1 R132.1 R134.2 R135.2 U22.B2(GND) U22.B3(GND) U22.B4(AGND) U22.C1(GND) U22.C2(GND) U22.C3(GND) U22.C4(GND) U23.B2(GND) U23.B3(GND) U23.B4(AGND) U23.C1(GND) U23.C2(GND) U23.C3(GND) U23.C4(GND) U24.B2(GND) U24.B3(GND) U24.B4(AGND) U24.C1(GND) U24.C2(GND) U24.C3(GND) U24.C4(GND) U25.2(GND) U26.2(GND) U27.2(GND)
VCC3V3_LCD: 6.2 U27.1(VOUT)
VCC4V0_SYS: C485.2 C493.2 C500.2 C501.2 C509.2 C510.2 R126.1 TP71.1(TP) U22.D1(VIN) U22.D2(VIN) U22.E1(VIN) U22.E2(VIN) U23.D1(VIN) U23.D2(VIN) U23.E1(VIN) U23.E2(VIN) U24.D1(VIN) U24.D2(VIN) U24.E1(VIN) U24.E2(VIN) U25.4(IN)  [project net VCC1]
VCC_1V1_NLDO_S3: C517.2 C518.1 C519.1 L22.2 R125.1 TP76.1(TP)  [project net VCC14]
VCC_1V8_S0: R133.2
VCC_3V3_S0: 5.2 U26.1(VOUT)
VCC_3V3_S3: C520.2 C521.2 R122.2 U26.5(VIN) U27.5(VIN)  [project net EMMC_VCC]
VDD_CPU_BIG0_S0: C506.1 C507.1 R121.1 R308.2 U23.A4(VOUT) ; port VDD_CPU_BIG0_S0
VDD_CPU_BIG1_MEM_S0: C508.1 FB9.2
VDD_CPU_BIG1_S0: C498.1 C499.1 FB9.1 R120.1 R307.2 U22.A4(VOUT) ; port VDD_CPU_BIG1_S0
VDD_NPU_S0: C515.1 C516.1 R124.1 R309.2 U24.A4(VOUT) ; port VDD_NPU_S0
BIG/NPU_EN: R122.1 R123.2 U23.A2(EN) U24.A2(EN)
CPU_BIG0_VSEL: U23.A1(VSEL) ; port CPU_BIG0_VSEL
CPU_BIG1_VSEL: U22.A1(VSEL) ; port CPU_BIG1_VSEL
I2C0_SCL_M2: U22.A3(SCL) U23.A3(SCL) ; port I2C0_SCL_M2
I2C0_SDA_M2: U22.B1(SDA) U23.B1(SDA) ; port I2C0_SDA_M2
I2C1_SCL_M2: U24.A3(SCL) ; port I2C1_SCL_M2
I2C1_SDA_M2: U24.B1(SDA) ; port I2C1_SDA_M2
LCD_PWREN_H: R135.1 U27.4(EN) ; port LCD_PWREN_H
NPU_VSEL: U24.A1(VSEL) ; port NPU_VSEL
PMIC_EXT_EN_OUT: R127.2 ; port PMIC_EXT_EN_OUT
NetC494_1: C494.1 C495.1 C496.1 C497.1 C499.2 L19.2 R120.2 R307.1 TP72.1(TP)
NetC502_1: C502.1 C503.1 C504.1 C505.1 C507.2 L20.2 R121.2 R308.1 TP74.1(TP)
NetC511_1: C511.1 C512.1 C513.1 C514.1 C516.2 L21.2 R124.2 R309.1 TP75.1(TP)
NetC517_1: C517.1 R125.2 R129.2 U25.5(FB)
NetL19_1: L19.1 U22.D3(LX) U22.D4(LX) U22.E3(LX) U22.E4(LX)
NetL20_1: L20.1 U23.D3(LX) U23.D4(LX) U23.E3(LX) U23.E4(LX)
NetL21_1: L21.1 U24.D3(LX) U24.D4(LX) U24.E3(LX) U24.E4(LX)
NetL22_1: L22.1 U25.3(LX)
NetR127_1: R127.1 U25.1(EN)
NetR131_2: R131.2 U26.3(ILIM)
NetR132_2: R132.2 U27.3(ILIM)
NetR133_1: R133.1 R134.1 U26.4(EN)

Not connected (* = marked no-connect by the designer): U22 A2(EN)*

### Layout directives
net class Power: VCC1

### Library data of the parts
5 6 = CMP-001-00016-6: 10uF 50V X5R ±10% 1206 Multilayer Ceramic Capacitors MLCC - SMD/SMT ROHS; Voltage Rating: 50; MN: CL31A106KBHNNNE
C485 C493 C500 C501 C509 C510 = CMP-001-00081-4: 22uF 25V X5R ±20% 0805 Multilayer Ceramic Capacitors MLCC - SMD/SMT ROHS; Voltage Rating: 16V; Tolerance: 5%; MN: CL21A226MAQNNNE
C494-C498 C502-C506 C508 C511-C515 C518 = CMP-06035-063649-1: 10V 22uF X5R ±20% 0603 Multilayer Ceramic Capacitors MLCC - SMD/SMT ROHS; MN: CL10A226MP8NUNE
C499 C507 C516 = CMP-001-00063-3: Chip Capacitor, 1µF +/-20%, 10V, 0402, Thickness 0.6 mm; Tolerance: 10%; MN: CL05A105KP5NNNC
C517 = CMP-2008-01233-1: 100pF 50V X7R ±10% 0402 Multilayer Ceramic Capacitors MLCC - SMD/SMT ROHS; Manufacturer: Vitramon; MN: VJ0402Y101KXAPW1BC
C519 = CMP-2010-00672-2: as C454-C459 on sheet RK3588_USB2.0_USB3.0
C520 C521 = CMP-2006-01140-1: Part Number: VJ0603Y104MXXAC; Manufacturer: Vitramon
FB9 = CMP-0686-00554-8: FERRITE BEAD 120 OHM 0603 1LN; Max Current Rating: 3A; DC Resistance (DCR): 30mR; Impedance: 120R; Number of Lines: 1; Test Frequency: 100MHz; Tolerance: 25%
L19-L21 = CMP-0226-00096-3: INDUCTOR, 0.22UH, 27A, 20%; Product Range: WURTH ELEKTRONIK - WE-HCC Series; Indu; Core Material: Ferrite; Self Resonant Frequency: 280MHz; Test Frequency: 100kHz; Series Resistance: 530µΩ; Shielding: Shielded; Saturation Current: 82.9A; DC Resistance (DCR): 1.1mΩ
L22 = LVF404026-2R2M-N
R120 R121 R124 = CMP-009-00065-2: 100R 0.063W 1% 0402 (1005 Metric)  SMD; Power: 63mW; MN: 0402WGF1000TCE
R122 R125 R134 R135 = CMP-2002-07343-1: Part Number: RC0402FR-07100KL; Manufacturer: Yageo / Phycomp
R123 R129 = CMP-009-00068-2: 120K 0.063W 1% 0402 (1005 Metric)  SMD; Power: 63mW; MN: 0402WGF1203TCE
R126 = CMP-00621-81932632-1: CC0603KRX5R7BB106 Multilayer Ceramic Capacitor, 10 uF, 16 V, ± 10%, X5R, 0603 [1608 Metric]; Capacitance: 10µF; Voltage Rating: 16V
R127 R133 = CMP-2002-07353-1: as R107 on sheet HDMI
R131 R132 = CMP-009-00105-2: 4K7 0.063W 1% 0402 (1005 Metric)  SMD; Power: 63mW; MN: 0402WGF4701TCE
R307-R309 = CMP-009-00002-5: 10mΩ 1W Current Sense Resistor SMD ±1% ±100ppm/℃ 1206 Current Sense Resistors / Shunt Resistors ROHS; Tolerance: 5%; Voltage Rating: 200V
TP71 TP72 TP74-TP76 = CMP-00028-00002-2: 0.6mm round
U25 = SY8089AAC
U26 U27 = SGM2576YN5G/TR

## Sheet RS232 DBG_UART.SchDoc
size A; SheetNumber: 17; SheetTotal: 22
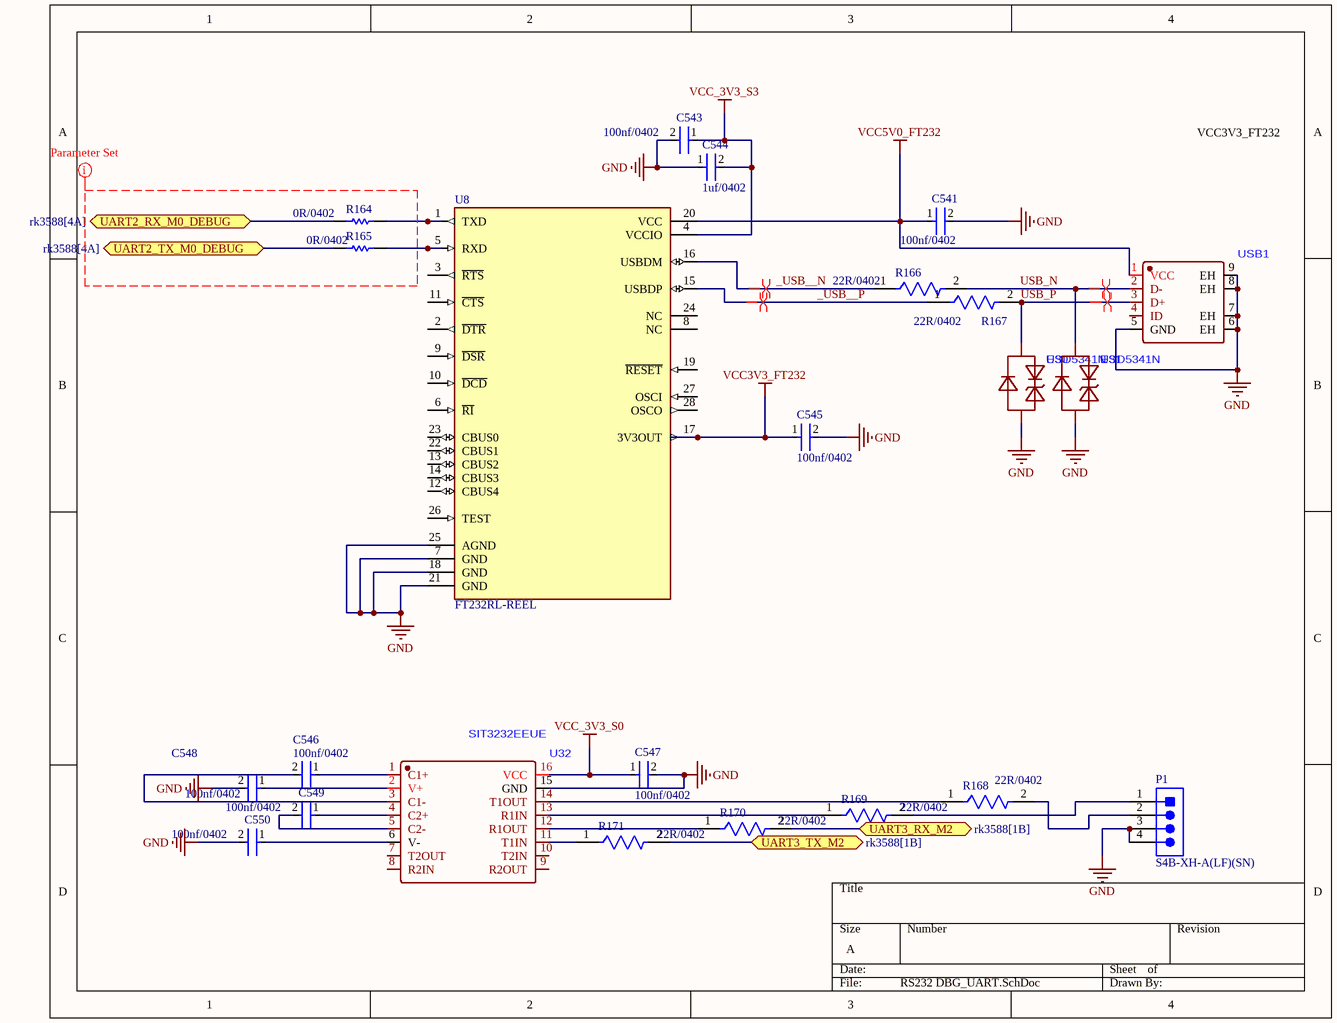
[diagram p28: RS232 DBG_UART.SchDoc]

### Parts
C541  100nf/0402  [FP-C0402-BB-MFG]
C543  100nf/0402  [FP-C0402-BB-MFG]
C544  1uf/0402  [FP-C0402C-BB-IPC_B]
C545  100nf/0402  [FP-C0402-BB-MFG]
C546  100nf/0402  [FP-C0402-BB-MFG]
C547  100nf/0402  [FP-C0402-BB-MFG]
C548  100nf/0402  [FP-C0402-BB-MFG]
C549  100nf/0402  [FP-C0402-BB-MFG]
C550  100nf/0402  [FP-C0402-BB-MFG]
P1  S4B-XH-A(LF)(SN)  [JST-S4B-XH-A(LF)(SN)_V]
R164  0R/0402  [RESC1005X40X25NL05T10]
R165  0R/0402  [RESC1005X40X25NL05T10]
R166  22R/0402  [FP-CRCW0402-e3-IPC_C]
R167  22R/0402  [FP-CRCW0402-e3-IPC_C]
R168  22R/0402  [FP-CRCW0402-e3-IPC_C]
R169  22R/0402  [FP-CRCW0402-e3-IPC_C]
R170  22R/0402  [FP-CRCW0402-e3-IPC_C]
R171  22R/0402  [FP-CRCW0402-e3-IPC_C]
U8  FT232RL-REEL  [FP-SSOP-28-MFG]
U30  ESD5341N  [DFN1006-2L-RD]
U31  ESD5341N  [DFN1006-2L-RD]
U32  SIT3232EEUE  [TSSOP-16_L5.0-W4.4-P0.65-LS6.4-BL]
USB1  (no value)  [MINI-USB-SMD_XY-5PTP-MINIUSB]

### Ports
UART2_RX_M0_DEBUG (bidir, see rk3588[4A]), UART2_TX_M0_DEBUG (bidir, see rk3588[4A]), UART3_RX_M2 (bidir, see rk3588[1B]), UART3_TX_M2 (bidir, see rk3588[1B])

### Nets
GND: C541.2 C543.2 C544.1 C545.2 C547.2 C548.2 C550.2 P1.3 P1.4 U8.7(GND) U8.18(GND) U8.21(GND) U8.25(AGND) U30.2 U31.2 U32.15(GND) USB1.5(GND) USB1.6(EH) USB1.7(EH) USB1.8(EH) USB1.9(EH)
VCC3V3_FT232: C545.1 U8.17(3V3OUT)
VCC5V0_FT232: C541.1 U8.20(VCC) USB1.1(VCC)
VCC_3V3_S0: C547.1 U32.16(VCC)
VCC_3V3_S3: C543.1 C544.2 U8.4(VCCIO)  [project net EMMC_VCC]
_USB__N: R166.1 U8.16(USBDM)
_USB__P: R167.1 U8.15(USBDP)
UART2_RX_M0_DEBUG: R164.1 ; port UART2_RX_M0_DEBUG
UART2_TX_M0_DEBUG: R165.1 ; port UART2_TX_M0_DEBUG
UART3_RX_M2: R170.2 ; port UART3_RX_M2
UART3_TX_M2: R171.2 ; port UART3_TX_M2
USB_N: R166.2 U31.1 USB1.2(D-)
USB_P: R167.2 U30.1 USB1.3(D+)
NetC546_1: C546.1 U32.1(C1+)
NetC546_2: C546.2 U32.3(C1-)
NetC548_1: C548.1 U32.2(V+)
NetC549_1: C549.1 U32.4(C2+)
NetC549_2: C549.2 U32.5(C2-)
NetC550_1: C550.1 U32.6(V-)
NetP1_1: P1.1 R169.2
NetP1_2: P1.2 R168.2
NetR164_2: R164.2 U8.1(TXD)
NetR165_2: R165.2 U8.5(RXD)
NetR168_1: R168.1 U32.14(T1OUT)
NetR169_1: R169.1 U32.13(R1IN)
NetR170_1: R170.1 U32.12(R1OUT)
NetR171_1: R171.1 U32.11(T1IN)

Not connected (* = marked no-connect by the designer): U8 2(~{DTR}) 3(~{RTS}) 6(~{RI}) 8(NC) 9(~{DSR}) 10(~{DCD}) 11(~{CTS}) 12(CBUS4) 13(CBUS2) 14(CBUS3) 19(~{RESET}) 22(CBUS1) 23(CBUS0) 24(NC) 26(TEST) 27(OSCI) 28(OSCO); U32 7(T2OUT) 8(R2IN) 9(R2OUT) 10(T2IN); USB1 4(ID)

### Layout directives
differential pair; differential pair class DBG_UART: _USB__N, _USB__P, USB_N, USB_P
net class RK_50OHM: (no net found under the mark)

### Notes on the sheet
- VCC3V3_FT232

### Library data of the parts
C541 C543 C545-C550 = CMP-2008-03082-2: CAP CER 0.1UF 16V X7R 0402; Manufacturer Part Number: C0402C104K4RACAUTO; Manufacturer: Kemet; Temperature Coefficient: 15%; Tolerance: 0.1; Capacitance: 0.10 μF; Material: Ceramic; Value: 0.10 μF
C544 = CMP-03020-034679-1: CAP CER 1UF 16V X5R 0402; Dielectric Material: Ceramic; Tolerance: 10%
P1 = CMP-002-00034-2: Male Header, Pitch 2.5 mm, 1 x 4 Position, Height 6.1 mm, Tail Length 3.4 mm, -25 to 85 degC, RoHS, Bulk; Manufacturer: JST
R164 R165 = CMP-2002-06970-1: -55℃~+155℃ 0Ω 62.5mW Thick Film Resistor ±5% 0402 Chip Resistor - Surface Mount ROHS; Part Number: RC0402JR-100RL; Manufacturer: Yageo
R166-R171 = CMP-02407-004337-1: RES Thick Film, 22Ω, 1%, 0.063W, 100ppm/°C, 0402; Resistance: 22R; Max Power Dissipation: 63mW
U8 = CMP-0078-00029-4: IC USB FS SERIAL UART 28-SSOP; Data Rate: 12Mbps; Max Supply Voltage: 5.25V; Operating Supply Current: 15mA; Number of Channels: 1; Voltage: 5V; Min Supply Voltage: 3.3V
USB1 = HMT-MINIUSB-5PTP

## Sheet Key Array.SchDoc
size B; SheetNumber: 18; SheetTotal: 22
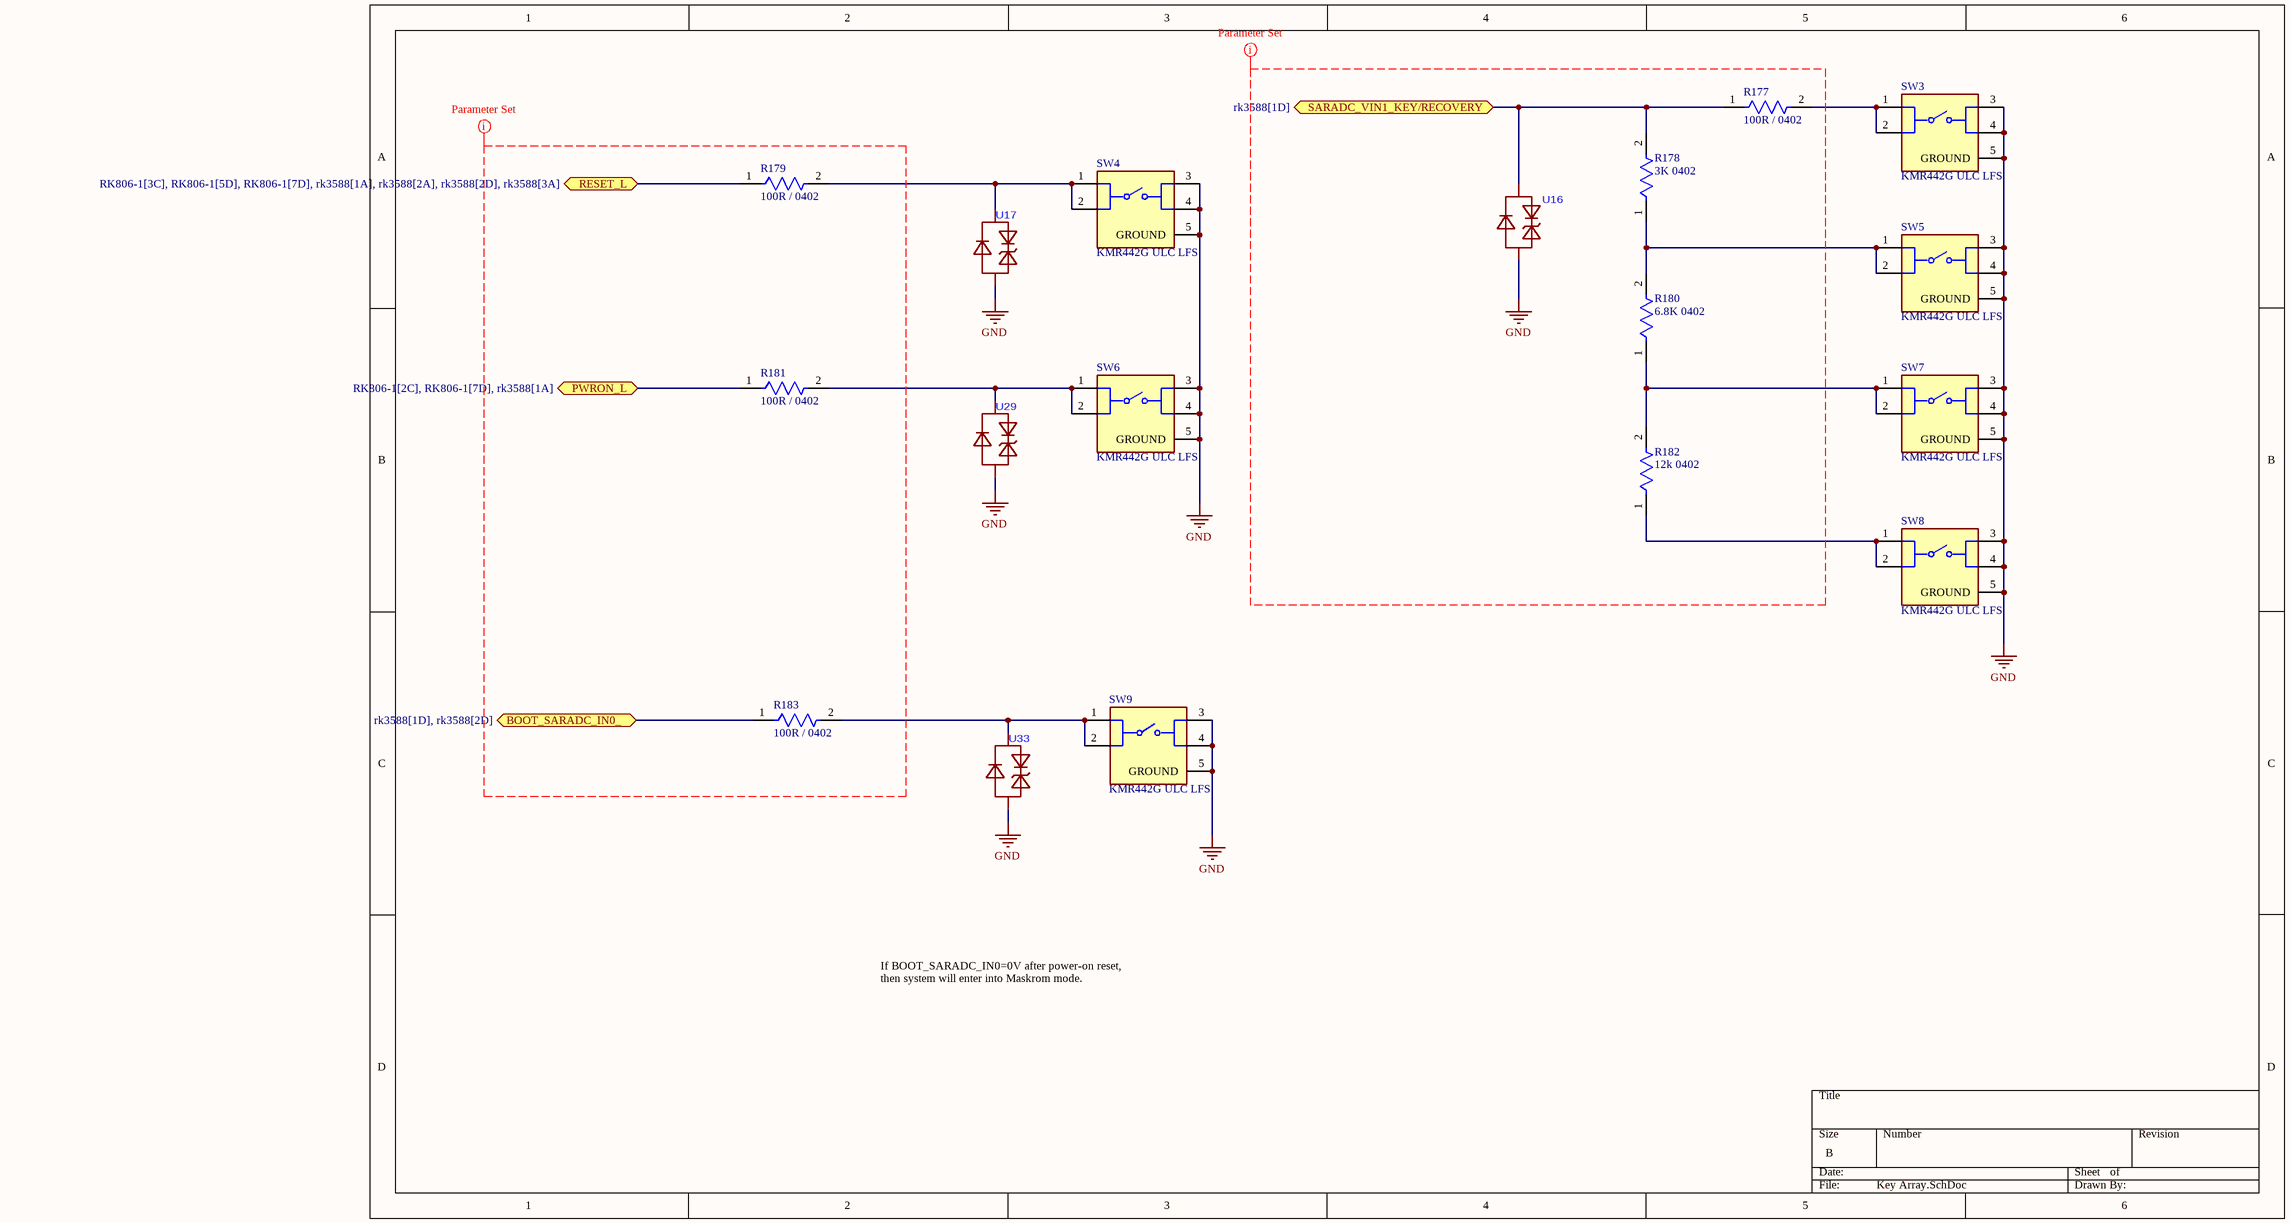
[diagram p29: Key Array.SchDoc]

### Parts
R177  100R / 0402  [FP-MCS0402-IPC_C]
R178  3K 0402  [FP-AT0402-IPC_B]
R179  100R / 0402  [FP-MCS0402-IPC_C]
R180  6.8K 0402  [FP-AC0402-MFG]
R181  100R / 0402  [FP-MCS0402-IPC_C]
R182  12k 0402  [FP-CRCW0402-e3-MFG]
R183  100R / 0402  [FP-MCS0402-IPC_C]
SW3  KMR442G ULC LFS  [FP-KMR442G_ULC_LFS-MFG]
SW4  KMR442G ULC LFS  [FP-KMR442G_ULC_LFS-MFG]
SW5  KMR442G ULC LFS  [FP-KMR442G_ULC_LFS-MFG]
SW6  KMR442G ULC LFS  [FP-KMR442G_ULC_LFS-MFG]
SW7  KMR442G ULC LFS  [FP-KMR442G_ULC_LFS-MFG]
SW8  KMR442G ULC LFS  [FP-KMR442G_ULC_LFS-MFG]
SW9  KMR442G ULC LFS  [FP-KMR442G_ULC_LFS-MFG]
U16  (no value)  [DFN1006-2L-RD]
U17  (no value)  [DFN1006-2L-RD]
U29  (no value)  [DFN1006-2L-RD]
U33  (no value)  [DFN1006-2L-RD]

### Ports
BOOT_SARADC_IN0_ (bidir, see rk3588[1D], rk3588[2D]), PWRON_L (bidir, see RK806-1[2C], RK806-1[7D], rk3588[1A]), RESET_L (bidir, see RK806-1[3C], RK806-1[5D], RK806-1[7D], rk3588[1A], rk3588[2A], rk3588[2D], rk3588[3A]), SARADC_VIN1_KEY/RECOVERY (bidir, see rk3588[1D])

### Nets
GND: SW3.3 SW3.4 SW3.5(GROUND) SW4.3 SW4.4 SW4.5(GROUND) SW5.3 SW5.4 SW5.5(GROUND) SW6.3 SW6.4 SW6.5(GROUND) SW7.3 SW7.4 SW7.5(GROUND) SW8.3 SW8.4 SW8.5(GROUND) SW9.3 SW9.4 SW9.5(GROUND) U16.2 U17.2 U29.2 U33.2
BOOT_SARADC_IN0_: R183.1 ; port BOOT_SARADC_IN0_
PWRON_L: R181.1 ; port PWRON_L
RESET_L: R179.1 ; port RESET_L
SARADC_VIN1_KEY/RECOVERY: R177.1 R178.2 U16.1 ; port SARADC_VIN1_KEY/RECOVERY
NetR177_2: R177.2 SW3.1 SW3.2
NetR178_1: R178.1 R180.2 SW5.1 SW5.2
NetR179_2: R179.2 SW4.1 SW4.2 U17.1
NetR180_1: R180.1 R182.2 SW7.1 SW7.2
NetR181_2: R181.2 SW6.1 SW6.2 U29.1
NetR182_1: R182.1 SW8.1 SW8.2
NetR183_2: R183.2 SW9.1 SW9.2 U33.1

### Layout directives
net class RK_50OHM: (no net found under the mark), GND

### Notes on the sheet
- If BOOT_SARADC_IN0=0V after power-on reset,
  then system will enter into Maskrom mode.

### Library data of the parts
R177 R179 R181 R183 = CMP-02407-010762-1: RES SMD 1.2K OHM 1% 1/10W 0402; Voltage Rating: 50V; Max Power Dissipation: 100mW; Temperature Coefficient: 50ppm/°C
R178 = CMP-03412-044565-1: Thin Film Chip Resistors Automotive Grade 3kΩ 1% 50ppm/°C 0402; MP: AT0402FRE073KL
R180 = CMP-03412-047267-1: RES 6.8kΩ ±5% 0.125W 0402; MP: AC0402JR-7W6K8L
R182 = CMP-02407-010136-1: RES Thick Film, 12kΩ, 1%, 0.063W, 100ppm/°C, 0402; Max Power Dissipation: 63mW; Resistance: 12kR; MP: CRCW040212K0FKEE
SW3-SW9 = CMP-10040-000021-1: SWITCH TACTILE SPST-NO 0.05A 32V; Actuator Type: Standard; Actuator Length: 1.1mm; Max Current Rating: 50mA; Illumination Type: Non-Illuminated; Operating Force: 4N; Switch Travel: 0.35mm; Throw Configuration: SPST; Switch Function: Off-Mom; Mechanical Life: 200000Cycles; Power Rating: 1W
U16 U17 U29 U33 = ESD5341N

## Sheet RP2350.SchDoc
size B; SheetNumber: 19; SheetTotal: 22
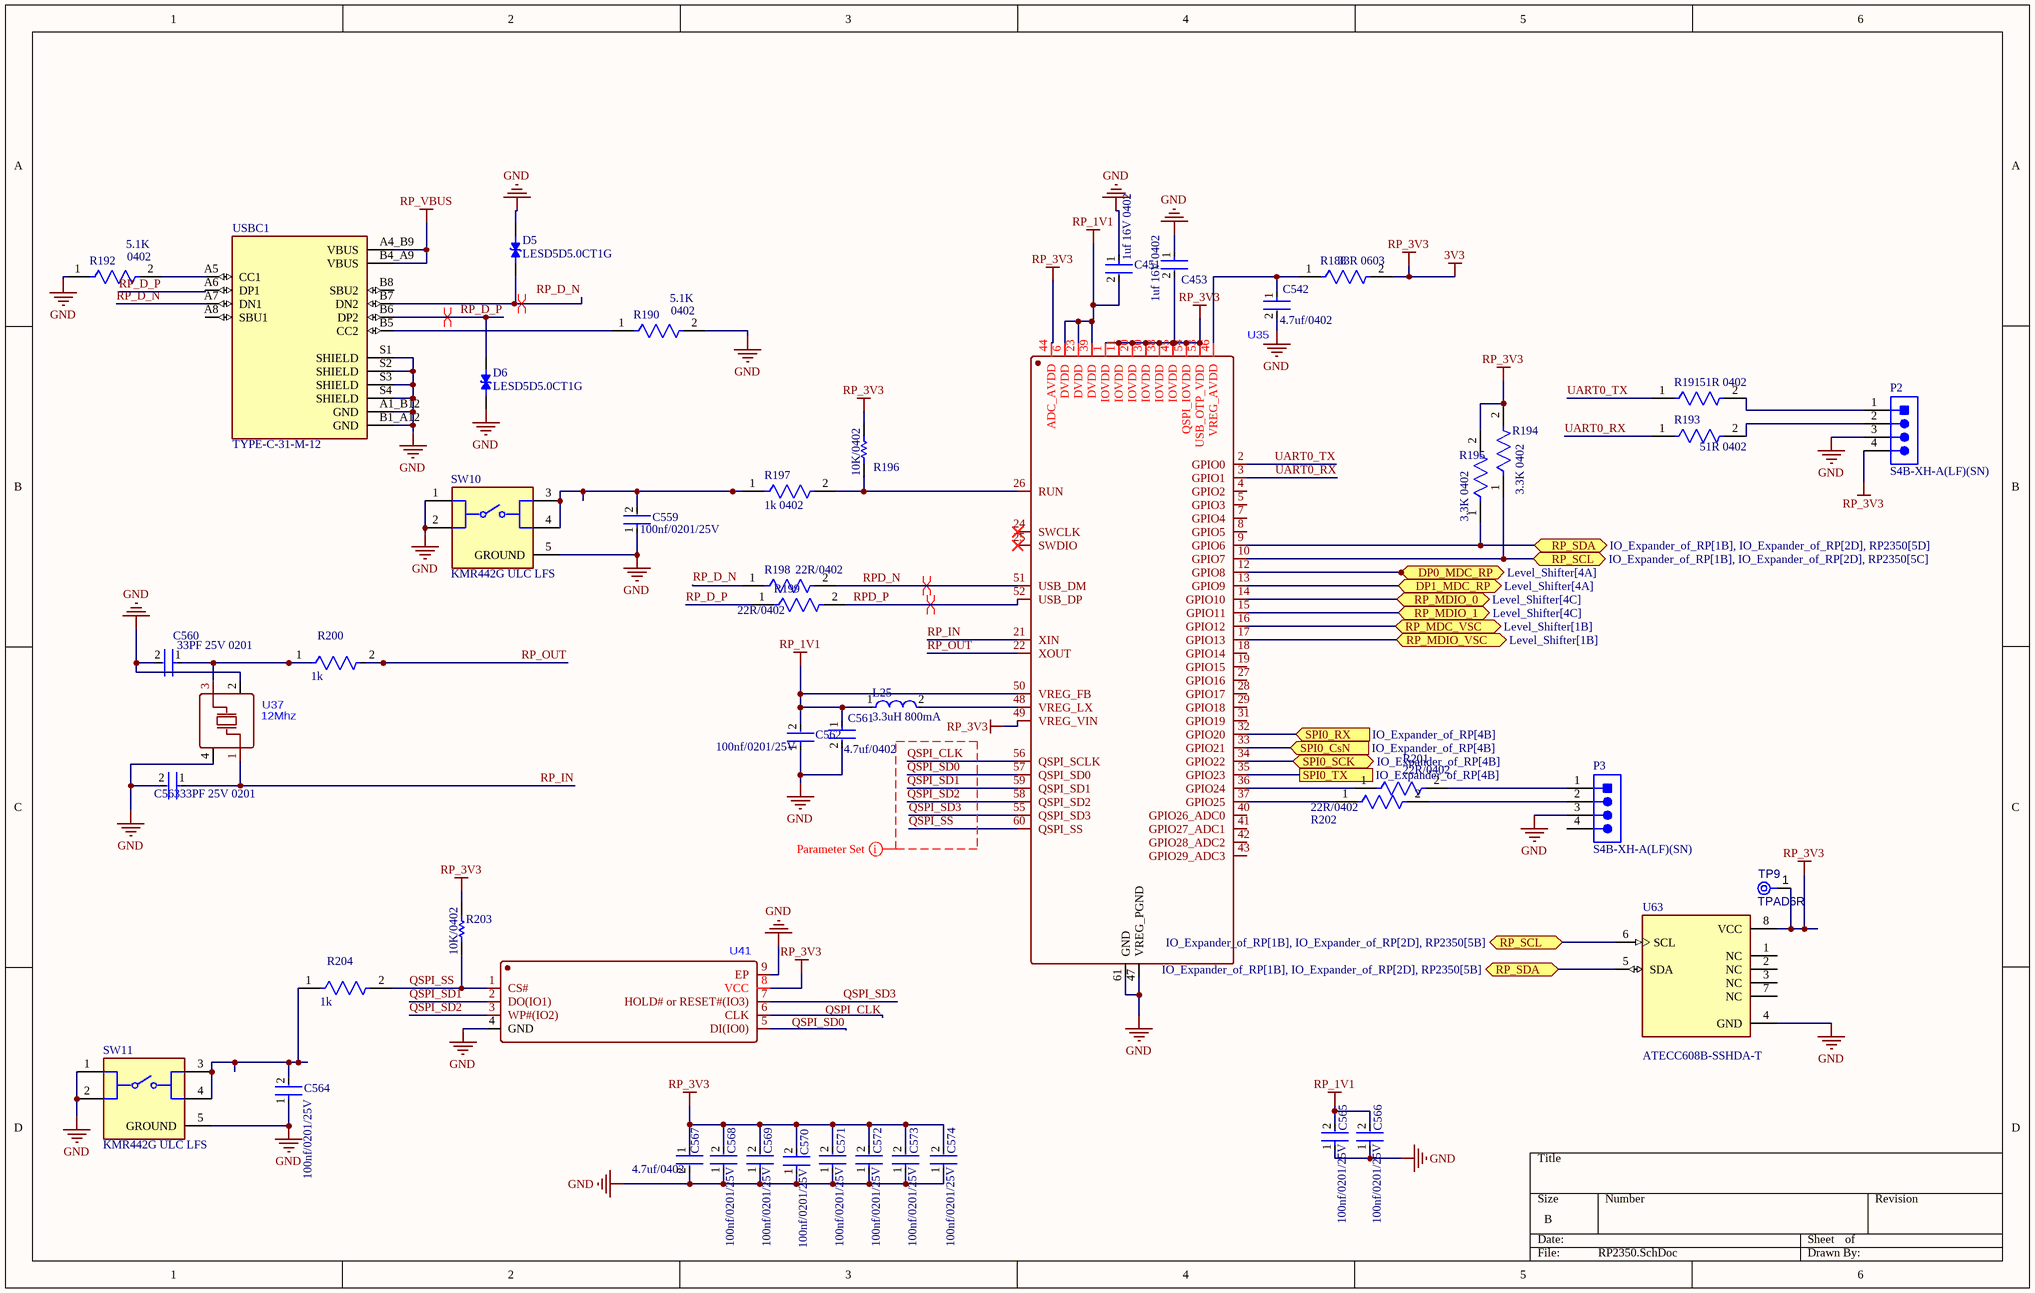
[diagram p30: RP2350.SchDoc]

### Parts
C451  1uf 16V 0402  [FP-0402-L_1_0_1-W_0_5_0_1-MFG]
C453  1uf 16V 0402  [FP-0402-L_1_0_1-W_0_5_0_1-MFG]
C542  4.7uf/0402  [FP-CC0402-MFG]
C559  100nf/0201/25V  [FP-CL03-IPC_C]
C560  33PF 25V 0201  [FP-C0201-AB-MFG]
C561  4.7uf/0402  [FP-CC0402-MFG]
C562  100nf/0201/25V  [FP-CL03-IPC_C]
C563  33PF 25V 0201  [FP-C0201-AB-MFG]
C564  100nf/0201/25V  [FP-CL03-IPC_C]
C565  100nf/0201/25V  [FP-CL03-IPC_C]
C566  100nf/0201/25V  [FP-CL03-IPC_C]
C567  4.7uf/0402  [FP-CC0402-MFG]
C568  100nf/0201/25V  [FP-CL03-IPC_C]
C569  100nf/0201/25V  [FP-CL03-IPC_C]
C570  100nf/0201/25V  [FP-CL03-IPC_C]
C571  100nf/0201/25V  [FP-CL03-IPC_C]
C572  100nf/0201/25V  [FP-CL03-IPC_C]
C573  100nf/0201/25V  [FP-CL03-IPC_C]
C574  100nf/0201/25V  [FP-CL03-IPC_C]
D5  LESD5D5.0CT1G  [TVS_LESD5D5.0CT1G]
D6  LESD5D5.0CT1G  [TVS_LESD5D5.0CT1G]
L25  3.3uH 800mA  [FP-CB2016-MFG]
P2  S4B-XH-A(LF)(SN)  [JST-S4B-XH-A(LF)(SN)_V]
P3  S4B-XH-A(LF)(SN)  [JST-S4B-XH-A(LF)(SN)_V]
R188  33R 0603  [FP-AF0603-IPC_C]
R190  value 5.1K  Case/Package: 0402  [FP-RN73R1E-IPC_C]  (hidden comment: 5.1K 0402)
R191  51R 0402  [FP-AF0402-IPC_C]
R192  value 5.1K  Case/Package: 0402  [FP-RN73R1E-IPC_C]  (hidden comment: 5.1K 0402)
R193  51R 0402  [FP-AF0402-IPC_C]
R194  3.3K 0402  [FP-RN73R1E-IPC_B]
R195  3.3K 0402  [FP-RN73R1E-IPC_B]
R196  10K/0402  [RESC1005X40X20NL05T10]
R197  1k 0402  [FP-MCS0402-IPC_C]
R198  22R/0402  [FP-CRCW0402-e3-IPC_C]
R199  22R/0402  [FP-CRCW0402-e3-IPC_C]
R200  1k  [FP-CRGCQ0402-IPC_C]
R201  22R/0402  [FP-CRCW0402-e3-IPC_C]
R202  22R/0402  [FP-CRCW0402-e3-IPC_C]
R203  10K/0402  [RESC1005X40X20NL05T10]
R204  1k  [FP-CRGCQ0402-IPC_C]
SW10  KMR442G ULC LFS  [FP-KMR442G_ULC_LFS-MFG]
SW11  KMR442G ULC LFS  [FP-KMR442G_ULC_LFS-MFG]
TP9  TPAD6R  [TP06R]  (no BOM)
U35  (no value)  [QFN-60_L7.0-W7.0-P0.40-TL-EP3.4]
U37  12Mhz  [CRYSTAL-SMD_4P-L3.2-W2.5-BL]
U41  (no value)  [WSON-8_L6.0-W8.0-P1.27-BL-EP]
U63  ATECC608B-SSHDA-T  [SOIC127P600X175-8N]
USBC1  TYPE-C-31-M-12  [HRO_TYPE-C-31-M-12]

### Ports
DP0_MDC_RP (bidir, see Level_Shifter[4A]), DP1_MDC_RP (bidir, see Level_Shifter[4A]), RP_MDC_VSC (bidir, see Level_Shifter[1B]), RP_MDIO_0 (bidir, see Level_Shifter[4C]), RP_MDIO_1 (bidir, see Level_Shifter[4C]), RP_MDIO_VSC (bidir, see Level_Shifter[1B]), RP_SCL (bidir, see IO_Expander_of_RP[1B], IO_Expander_of_RP[2D], RP2350[5B]), RP_SCL (bidir, see IO_Expander_of_RP[1B], IO_Expander_of_RP[2D], RP2350[5C]), RP_SDA (bidir, see IO_Expander_of_RP[1B], IO_Expander_of_RP[2D], RP2350[5B]), RP_SDA (bidir, see IO_Expander_of_RP[1B], IO_Expander_of_RP[2D], RP2350[5D]), SPI0_CsN (in, see IO_Expander_of_RP[4B]), SPI0_RX (in, see IO_Expander_of_RP[4B]), SPI0_SCK (bidir, see IO_Expander_of_RP[4B]), SPI0_TX (see IO_Expander_of_RP[4B])

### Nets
3V3: C453.2 C567.1 C568.2 C569.2 C570.2 C571.2 C572.2 C573.2 C574.2 P2.4 R188.2 R194.2 R195.2 R196.2 R203.2 TP9.1(TP) U35.1(IOVDD) U35.11(IOVDD) U35.20(IOVDD) U35.30(IOVDD) U35.38(IOVDD) U35.44(ADC_AVDD) U35.45(IOVDD) U35.49(VREG_VIN) U35.53(USB_OTP_VDD) U35.54(QSPI_IOVDD) U41.8(VCC) U63.8(VCC)  [also labelled RP_3V3]
GND: C451.1 C453.1 C542.2 C559.1 C560.2 C561.2 C562.1 C563.2 C564.1 C565.1 C566.1 C567.2 C568.1 C569.1 C570.1 C571.1 C572.1 C573.1 C574.1 D5.1 D6.2 P2.3 P3.3 R190.2 R192.1 SW10.1 SW10.2 SW10.5(GROUND) SW11.1 SW11.2 SW11.5(GROUND) U35.47(VREG_PGND) U35.61(GND) U37.2(GND) U37.4(GND) U41.4(GND) U41.9(EP) U63.4(GND) USBC1.A1_B12(GND) USBC1.B1_A12(GND) USBC1.S1(SHIELD) USBC1.S2(SHIELD) USBC1.S3(SHIELD) USBC1.S4(SHIELD)
RP_1V1: C451.2 C561.1 C562.2 C565.2 C566.2 L25.1 U35.6(DVDD) U35.23(DVDD) U35.39(DVDD) U35.50(VREG_FB)
RP_VBUS: USBC1.A4_B9(VBUS) USBC1.B4_A9(VBUS)
DP0_MDC_RP: U35.12(GPIO8) ; port DP0_MDC_RP
DP1_MDC_RP: U35.13(GPIO9) ; port DP1_MDC_RP
QSPI_CLK: U35.56(QSPI_SCLK) U41.6(CLK)
QSPI_SD0: U35.57(QSPI_SD0) U41.5(DI(IO0))
QSPI_SD1: U35.59(QSPI_SD1) U41.2(DO(IO1))
QSPI_SD2: U35.58(QSPI_SD2) U41.3(WP#(IO2))
QSPI_SD3: U35.55(QSPI_SD3) U41.7(HOLD#_or_RESET#(IO3))
QSPI_SS: R203.1 R204.2 U35.60(QSPI_SS) U41.1(CS#)
RP_D_N: D5.2 R198.1 USBC1.A7(DN1) USBC1.B7(DN2)
RP_D_P: D6.1 R199.1 USBC1.A6(DP1) USBC1.B6(DP2)
RP_IN: C563.1 U35.21(XIN) U37.1(XTAL)
RP_MDC_VSC: U35.16(GPIO12) ; port RP_MDC_VSC
RP_MDIO_0: U35.14(GPIO10) ; port RP_MDIO_0
RP_MDIO_1: U35.15(GPIO11) ; port RP_MDIO_1
RP_MDIO_VSC: U35.17(GPIO13) ; port RP_MDIO_VSC
RP_OUT: R200.2 U35.22(XOUT)
RP_SCL: R194.1 U35.10(GPIO7) U63.6(SCL) ; port RP_SCL
RP_SDA: R195.1 U35.9(GPIO6) U63.5(SDA) ; port RP_SDA
RPD_N: R198.2 U35.51(USB_DM)
RPD_P: R199.2 U35.52(USB_DP)
SPI0_CsN: U35.33(GPIO21) ; port SPI0_CsN
SPI0_RX: U35.32(GPIO20) ; port SPI0_RX
SPI0_SCK: U35.34(GPIO22) ; port SPI0_SCK
SPI0_TX: U35.35(GPIO23) ; port SPI0_TX
UART0_RX: R193.1 U35.3(GPIO1)
UART0_TX: R191.1 U35.2(GPIO0)
NetC542_1: C542.1 R188.1 U35.46(VREG_AVDD)
NetC559_2: C559.2 R197.1 SW10.3 SW10.4
NetC560_1: C560.1 R200.1 U37.3(XTAL)
NetC564_2: C564.2 R204.1 SW11.3 SW11.4
NetL25_2: L25.2 U35.48(VREG_LX)
NetP2_1: P2.1 R191.2
NetP2_2: P2.2 R193.2
NetP3_1: P3.1 R201.2
NetP3_2: P3.2 R202.2
NetR190_1: R190.1 USBC1.B5(CC2)
NetR192_2: R192.2 USBC1.A5(CC1)
NetR196_1: R196.1 R197.2 U35.26(RUN)
NetR201_1: R201.1 U35.36(GPIO24)
NetR202_1: R202.1 U35.37(GPIO25)

Not connected (* = marked no-connect by the designer): P3 4; U35 4(GPIO2) 5(GPIO3) 7(GPIO4) 8(GPIO5) 18(GPIO14) 19(GPIO15) 24(SWCLK)* 25(SWDIO)* 27(GPIO16) 28(GPIO17) 29(GPIO18) 31(GPIO19) 40(GPIO26_ADC0) 41(GPIO27_ADC1) 42(GPIO28_ADC2) 43(GPIO29_ADC3); U63 1(NC) 2(NC) 3(NC) 7(NC); USBC1 A8(SBU1) B8(SBU2)

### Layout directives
differential pair; differential pair class RP_USB: RP_D_N, RP_D_P, RPD_N, RPD_P
net class QSPI_RPI: QSPI_CLK, QSPI_SD0, QSPI_SD1, QSPI_SD2, QSPI_SD3, QSPI_SS

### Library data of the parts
C451 C453 = CMP-04427-002736-1: General Purpose Ceramic Capacitor, 0402, 1uF, 20%, X5R, 15%, 16V
C542 C561 C567 = CMP-03422-000823-1: as C463 on sheet HDMI
C559 C562 C564-C566 C568-C574 = CMP-2010-00672-2: as C454-C459 on sheet RK3588_USB2.0_USB3.0
C560 C563 = CMP-03020-034488-1: CAP CER 33PF 25V NP0 0201; Manufacturer Part Number: C0201C330K3GACTU; Manufacturer: KEMET; Standoff Height: 0mm; Tolerance: 0.1; Temperature Characteristic: C0G; Temperature Coefficient: 30ppm/°C; Material: Ceramic
D5 D6 = CMP-027-000000-1: Transient Voltage Suppressors for ESD Protection; MF: Leshan Radio Co.
L25 = CMP-14484-000214-1: SMD Inductors 3.3uH ±20% 0.8A 0.26Ω 0806; DC Resistance (DCR): 260mR; Saturation Current: 400mA; Test Frequency: 7.96MHz; Shielding: Unshielded; Core Material: Ferrite; Self Resonant Frequency: 55MHz
P2 P3 = CMP-002-00034-2: as P1 on sheet RS232 DBG_UART
R188 = CMP-03412-046795-1: Anti-Sulfurated Chip Resistors Automotive Grade 33Ω 1% 100ppm/°C 0603; Max Power Dissipation: 100mW; MN: AF0603FR-0733RL
R190 R192 = CMP-04015-008529-1: 5.1kΩ ±1% 0.063W, 1/16W Chip Resistor 0402 (1005 Metric) Moisture Resistant Thin Film; MN: RN73R1ETTP5101F25
R191 R193 = CMP-03412-039875-1: Anti-Sulfurated Chip Resistors Automotive Grade 51Ω 5% 100ppm/°C 0402; Max Power Dissipation: 63mW
R194 R195 = CMP-04015-026447-1: 3.3kΩ ±1% 0.063W, 1/16W Chip Resistor 0402 (1005 Metric) Moisture Resistant Thin Film
R196 R203 = CMP-2002-01682-1: Manufacturer: Vishay BCcomponents; Part Number: TNPW040210K0DEED
R197 = CMP-2002-02445-2: RES SMD 1.2K OHM 1% 1/10W 0402; Resistance: 1kR; Tolerance: 0.1%; Max Power Dissipation: 63mW; Temperature Coefficient: 25ppm/°C; MN: MCS04020D1001BE000
R198 R199 R201 R202 = CMP-02407-004337-1: as R166 on sheet RS232 DBG_UART
R200 R204 = CMP-03211-006314-1: CRGCQ0402 1KΩ 1% ±100ppm/°C 50V; Manufacturer Part Number: CRGCQ0402F1K0; Manufacturer: TE Connectivity; Power Rating: 0.0625W; Tolerance: 0.01
SW10 SW11 = CMP-10040-000021-1: as SW3 on sheet Key Array
TP9 = CMP-00028-00002-2: 0.6mm round
U35 = RP2350A
U37 = C9002: MN: ABM8-272-T3
U41 = W25Q128JVEIQ TR
U63 = ATECC608B-SSHDA-T: Security ICs / Authentication ICs ECC/ECDH, I2C, SOIC T/R; MF: Microchip Technology
USBC1 = TYPE-C-31-M-12: USB Connectors 24 Receptacle 1 8.94*7.3mm RoHS; MF: HRO Electronics Co., Ltd.

## Sheet IO_Expander_of_RP.SchDoc
size C; SheetNumber: 20; SheetTotal: 22
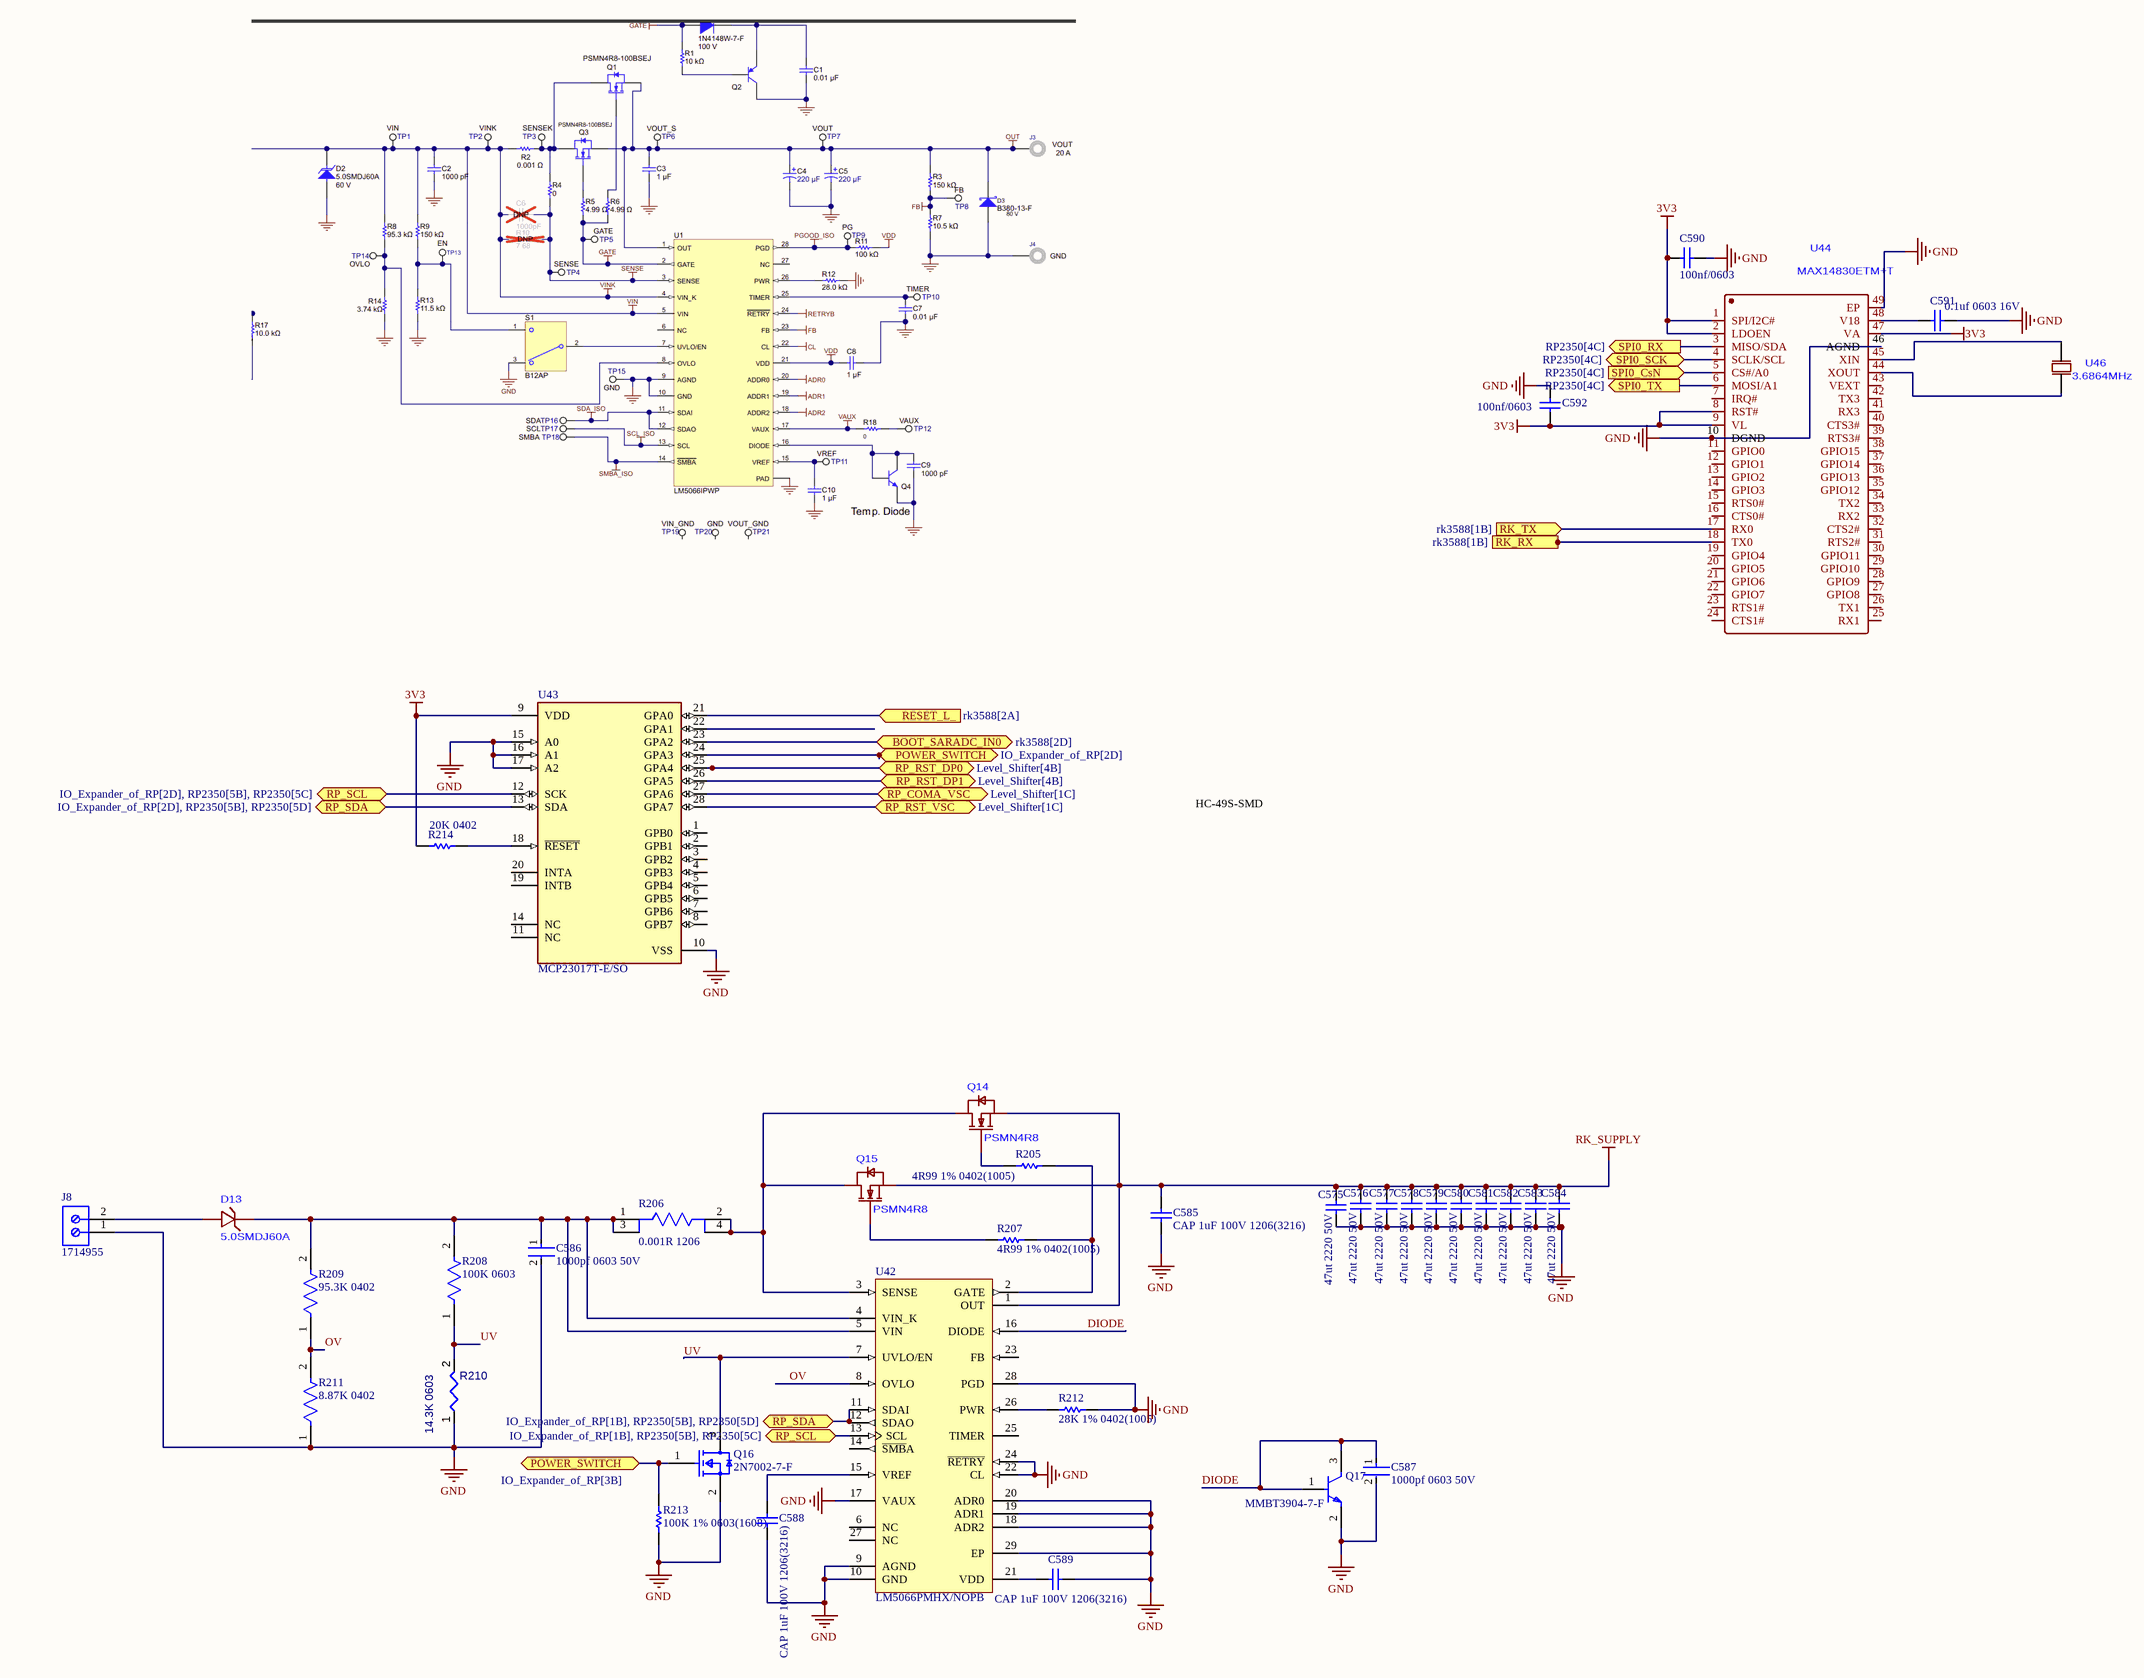
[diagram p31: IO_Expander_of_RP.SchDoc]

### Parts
C575  47ut 2220 50V  [CAPC2220(5750)230_N]
C576  47ut 2220 50V  [CAPC2220(5750)230_N]
C577  47ut 2220 50V  [CAPC2220(5750)230_N]
C578  47ut 2220 50V  [CAPC2220(5750)230_N]
C579  47ut 2220 50V  [CAPC2220(5750)230_N]
C580  47ut 2220 50V  [CAPC2220(5750)230_N]
C581  47ut 2220 50V  [CAPC2220(5750)230_N]
C582  47ut 2220 50V  [CAPC2220(5750)230_N]
C583  47ut 2220 50V  [CAPC2220(5750)230_N]
C584  47ut 2220 50V  [CAPC2220(5750)230_N]
C585  CAP 1uF 100V 1206(3216)  [CAPC1206(3216)190_M]
C586  1000pf 0603 50V  [FP-C0603C-CF-MFG]
C587  1000pf 0603 50V  [FP-C0603C-CF-MFG]
C588  CAP 1uF 100V 1206(3216)  [CAPC1206(3216)190_M]
C589  CAP 1uF 100V 1206(3216)  [CAPC1206(3216)190_M]
C590  100nf/0603  [CAPC1608X92X38ML15T08]
C591  0.1uf 0603 16V  [CAPC1608X90X35NL15T15]
C592  100nf/0603  [CAPC1608X92X38ML15T08]
D13  5.0SMDJ60A  [SMC_L6.9-W5.9-LS7.9-RD]
J8  1714955  [PHOE-1714955_V]
Q14  PSMN4R8  [TO-263-2_L10.2-W8.5-P2.54-LS15.2-TL]
Q15  PSMN4R8  [TO-263-2_L10.2-W8.5-P2.54-LS15.2-TL]
Q16  2N7002-7-F  [FP-SOT23-MFG]
Q17  MMBT3904-7-F  [FP-SOT23-IPC_A]
R205  4R99 1% 0402(1005)  [RESC0402(1005)_L]
R206  0.001R 1206  [FP-PS0612-MFG]
R207  4R99 1% 0402(1005)  [RESC0402(1005)_L]
R208  100K 0603  [FP-TFCR0603-IPC_B]
R209  95.3K 0402  [FP-RP73P-1E-MFG]
R210  14.3K 0603  [RESC0603(1608)_L]
R211  8.87K 0402  [FP-RC1005-IPC_A]
R212  28K 1% 0402(1005)  [RESC0402(1005)_L]
R213  100K 1% 0603(1608)  [RESC0603(1608)_N]
R214  20K 0402  [RESC1005X35X20ML05T10]
U42  LM5066PMHX/NOPB  [PWP0028A_L]
U43  MCP23017T-E/SO  [FP-C04-052-MFG]
U44  MAX14830ETM+T  [TQFN-48_L7.0-W7.0-P0.50-BL-EP5.5]
U46  3.6864MHz  [HC-49S_L11.4-W4.5-LS12.5]

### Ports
BOOT_SARADC_IN0 (bidir, see rk3588[2D]), POWER_SWITCH (bidir, see IO_Expander_of_RP[2D]), POWER_SWITCH (bidir, see IO_Expander_of_RP[3B]), RESET_L_ (in, see rk3588[2A]), RK_RX (out, see rk3588[1B]), RK_TX (in, see rk3588[1B]), RP_COMA_VSC (bidir, see Level_Shifter[1C]), RP_RST_DP0 (bidir, see Level_Shifter[4B]), RP_RST_DP1 (bidir, see Level_Shifter[4B]), RP_RST_VSC (bidir, see Level_Shifter[1C]), RP_SCL (bidir, see IO_Expander_of_RP[1B], RP2350[5B], RP2350[5C]), RP_SCL (bidir, see IO_Expander_of_RP[2D], RP2350[5B], RP2350[5C]), RP_SDA (bidir, see IO_Expander_of_RP[1B], RP2350[5B], RP2350[5D]), RP_SDA (bidir, see IO_Expander_of_RP[2D], RP2350[5B], RP2350[5D]), SPI0_CsN (in, see RP2350[4C]), SPI0_RX (out, see RP2350[4C]), SPI0_SCK (bidir, see RP2350[4C]), SPI0_TX (out, see RP2350[4C])

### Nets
3V3: C590.2 C592.2 R214.2 U43.9(VDD) U44.1(SPI/I2C#) U44.2(LDOEN) U44.8(RST#) U44.9(VL) U44.47(VA)
GND: C575.1 C576.1 C577.1 C578.1 C579.1 C580.1 C581.1 C582.1 C583.1 C584.1 C585.1 C586.2 C587.2 C588.1 C589.1 C590.1 C591.2 C592.1 J8.1 Q16.2(S) Q17.2(E) R210.1 R211.1 R212.2 R213.1 U42.9(AGND) U42.10(GND) U42.17(VAUX) U42.18(ADR2) U42.19(ADR1) U42.20(ADR0) U42.22(CL) U42.24(~{RETRY}) U42.28(PGD) U42.29(EP) U43.10(VSS) U43.15(A0) U43.16(A1) U43.17(A2) U44.10(DGND) U44.46(AGND) U44.49(EP)
RK_SUPPLY: C575.2 C576.2 C577.2 C578.2 C579.2 C580.2 C581.2 C582.2 C583.2 C584.2 C585.2 Q14.3(S) Q15.3(S) U42.1(OUT)  [project net +24V]
BOOT_SARADC_IN0: U43.23(GPA2) ; port BOOT_SARADC_IN0
DIODE: C587.1 Q17.1(B) Q17.3(C) U42.16(DIODE)
OV: R209.1 R211.2 U42.8(OVLO)
POWER_SWITCH: Q16.1(G) R213.2 U43.24(GPA3) ; port POWER_SWITCH
RESET_L_: U43.21(GPA0) ; port RESET_L_
RK_RX: U44.18(TX0) ; port RK_RX
RK_TX: U44.17(RX0) ; port RK_TX
RP_COMA_VSC: U43.27(GPA6) ; port RP_COMA_VSC
RP_RST_DP0: U43.25(GPA4) ; port RP_RST_DP0
RP_RST_DP1: U43.26(GPA5) ; port RP_RST_DP1
RP_RST_VSC: U43.28(GPA7) ; port RP_RST_VSC
RP_SCL: U42.13(SCL) U43.12(SCK) ; port RP_SCL
RP_SDA: U42.11(SDAI) U42.12(SDAO) U43.13(SDA) ; port RP_SDA
SPI0_CsN: U44.5(CS#/A0) ; port SPI0_CsN
SPI0_RX: U44.3(MISO/SDA) ; port SPI0_RX
SPI0_SCK: U44.4(SCLK/SCL) ; port SPI0_SCK
SPI0_TX: U44.6(MOSI/A1) ; port SPI0_TX
UV: Q16.3(D) R208.1 R210.2 U42.7(UVLO/EN)
NetC586_1: C586.1 D13.1 R206.1 R206.3 R208.2 R209.2 U42.4(VIN_K) U42.5(VIN)
NetC588_2: C588.2 U42.15(VREF)
NetC589_2: C589.2 U42.21(VDD)
NetC591_1: C591.1 U44.48(V18)
NetD13_2: D13.2 J8.2
NetQ14_1: Q14.1(G) R205.1
NetQ14_2: Q14.2(D) Q15.2(D) R206.2 R206.4 U42.3(SENSE)
NetQ15_1: Q15.1(G) R207.1
NetR205_2: R205.2 R207.2 U42.2(GATE)
NetR212_1: R212.1 U42.26(PWR)
NetR214_1: R214.1 U43.18(~{RESET})
NetU44_44: U44.44(XOUT) U46.1(OSC1)
NetU44_45: U44.45(XIN) U46.2(OSC2)

Not connected (* = marked no-connect by the designer): U42 6(NC) 14(~{SMB}A) 23(FB) 25(TIMER) 27(NC); U43 1(GPB0) 2(GPB1) 3(GPB2) 4(GPB3) 5(GPB4) 6(GPB5) 7(GPB6) 8(GPB7) 11(NC) 14(NC) 19(INTB) 20(INTA) 22(GPA1); U44 7(IRQ#) 11(GPIO0) 12(GPIO1) 13(GPIO2) 14(GPIO3) 15(RTS0#) 16(CTS0#) 19(GPIO4) 20(GPIO5) 21(GPIO6) 22(GPIO7) 23(RTS1#) 24(CTS1#) 25(RX1) 26(TX1) 27(GPIO8) 28(GPIO9) 29(GPIO10) 30(GPIO11) 31(RTS2#) 32(CTS2#) 33(RX2) 34(TX2) 35(GPIO12) 36(GPIO13) 37(GPIO14) 38(GPIO15) 39(RTS3#) 40(CTS3#) 41(RX3) 42(TX3) 43(VEXT)

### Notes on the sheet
- HC-49S-SMD

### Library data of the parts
C575-C584 = CMP-1042-00650-1: CAP 470nF 200V ±10% 2220 (5750 Metric) Thickness 2.2mm SMD; MN: CKG57NX7R1H476MT009W; Tolerance: 20%; Case-EIA: 2220
C585 C588 C589 = CMP-1037-04727-1: CAP 1uF 100V ±5% 1206 (3216 Metric) Thickness 1.9mm SMD; Case-EIA: 1206; Tolerance: Â±5%; Case-Metric: 3216
C586 C587 = CMP-2006-03716-2: CAP CER 1000PF 50V X7R 0603; Manufacturer Part Number: C0603C102K5RACAUTO; Manufacturer: KEMET; Material: Ceramic; Automotive Grade: Grade 1; Value: 1,000 pF; Tolerance: 0.1; Temperature Coefficient: 30ppm/°C
C590 C592 = CMP-2006-01140-1: as C520 on sheet Discrete Power
C591 = CMP-2006-02299-1: Part Number: C0603C104K4RAC7013; Manufacturer: Kemet
J8 = CMP-2000-05797-1: PC Terminal Block, Pitch 6.35 mm, 1 x 2 Position, Height 21.5 mm, Tail Lenght 5.1 mm, RoHS, Bulk; Manufacturer: Phoenix Contact
Q14 Q15 = PSMN4R8-100BSEJ-VB
Q16 = CMP-2000-04929-2: MOSFET N-CH 60V 115MA SOT23-3; Turn-On Delay Time: 7ns; Turn-Off Delay Time: 11ns; Drain to Source Resistance: 7.5R; Rise Time: 3ns; Drain to Source Breakdown Voltage: 70V; Input Capacitance: 50pF; Number of Elements: 1; Power Dissipation: 540mW; Max Power Dissipation: 300mW; Fall Time: 5.6ns; Gate to Source Voltage (Vgs): 20V; Threshold Voltage: 2.5V; Element Configuration: Single
Q17 = CMP-2000-04931-2: TRANS NPN 40V 0.2A SMD SOT23-3; Frequency: 300MHz; Power Dissipation: 350mW; Element Configuration: Single; Max Power Dissipation: 300mW; Max Collector Current: 200mA; Collector Emitter Saturation Voltage: 300mV; Number of Elements: 1; hFE Min: 100; Collector Base Voltage (VCBO): 60V; Emitter Base Voltage (VEBO): 6V
R205 R207 = CMP-1011-00250-1: 4R99 0.063W 1% 0402 (1005 Metric)  SMD; Case-Metric: 1005; Value: 4.99 Ohm; Case-EIA: 0402
R206 = CMP-03412-024484-1: METAL CURRECT SENSOR 4 TERMINATI; Manufacturer Part Number: PS0612FKF070R001L; Manufacturer: Yageo; Value: 1mΩ; Temperature Coefficient: 100ppm/°C; Power Rating: 1W; Tolerance: 1%
R208 = CMP-250906-284575-1: RES Thin Film,  100kΩ, 0.1%, 0.1W, 25ppm/°C, 0603
R209 = CMP-03211-000534-1: RP73P 0402 95.3KΩ 0.1W 25ppm/°C 0.10% 50V; Manufacturer Part Number: RP73PF1E95K3BTDF; Manufacturer: TE Connectivity
R210 = CMP-009-00063-2: Jumper 0603 (1608 Metric); MN: 0603WAF1432T5E
R211 = CMP-13261-005100-1: Res Thick Film 0402 8.87kΩ 1% 0.063W ±100ppm/°C Molded SMD T/R; Voltage Rating (DC): 50V; Max Power Dissipation: 63mW; Resistance: 8.87kR
R212 = CMP-1011-00672-1: 28K 0.063W 1% 0402 (1005 Metric)  SMD; Case-Metric: 1005; Value: 28000.00 Ohm; Case-EIA: 0402
R213 = CMP-1012-00736-1: 100K 0.1W 1% 0603 (1608 Metric)  SMD; Value: 100000.00 Ohm; Case-Metric: 1608; Case-EIA: 0603
R214 = CMP-2002-03111-1: Part Number: 8-1879061-0; Manufacturer: TE Connectivity / AMP
U42 = CMP-0063-01545-2: High Voltage System Power Management and Protection IC with PMBus, 28-pin TSSOP-EP, 2500 Reel; Manufacturer: Texas Instruments; CompType: MiscPower; PackageTopMarking: NSUZXYTTE#*LM5066PMH; PowerWise: Y
U43 = CMP-0186-00060-3: IC I/O EXPANDER I2C 16B 28SOIC; Number of Channels: 1; Operating Supply Voltage: 5.5V; Max Frequency: 1.7MHz; Nominal Supply Current: 1mA; Number of Bits: 16
U44 = MAX14830ETM+T: -40℃~+85℃ 1.71V~3.6V、1.71V~3.6V、2.35V~3.6V 128Byte 12Mbps 4 I2C、SPI、IrDA、RS-485、RS-232 With automatic flow control、Configurable GPIO、Auto Transceiver Direction Control、Interrupt Trigger TQFN-48-EP(7x7) UART ROHS
U46 = SXMH3.6864F2020F30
